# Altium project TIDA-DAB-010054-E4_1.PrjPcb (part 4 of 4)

## Sheet TIDA-DAB-010054-E4_Power Tree.SchDoc
size 431 x 279 mm; Date: Not shown in title block; ApprovedBy: Not shown in title block; CheckedBy: Not shown in title block; Author: Not shown in title block; CompanyName: Not shown in title block; Engineer: Not shown in title block; Organization: Not shown in title block; Address1: Not shown in title block; Address2: Not shown in title block; Address3: Not shown in title block; Address4: Not shown in title block; DocumentNumber: 1; Revision: Use project parameter SCH_Rev; SheetNumber: 9; SheetTotal: 11; PageSetup: Record=PageOptions¦CenterHorizontal=True¦CenterVertical=True¦PrintScale=1.00¦XCorrection=1.00¦YCorrection=1.00¦PrintKind=0¦BorderSize=5000000¦LeftOffset=0¦BottomOffset=0¦Orientation=2¦PaperLength=1000¦PaperWidth=1000¦Scale=100¦PaperSource=15¦PrintQuality=600¦MediaType=1¦DitherType=10¦PaperKind=Letter¦PrintScaleMode=1
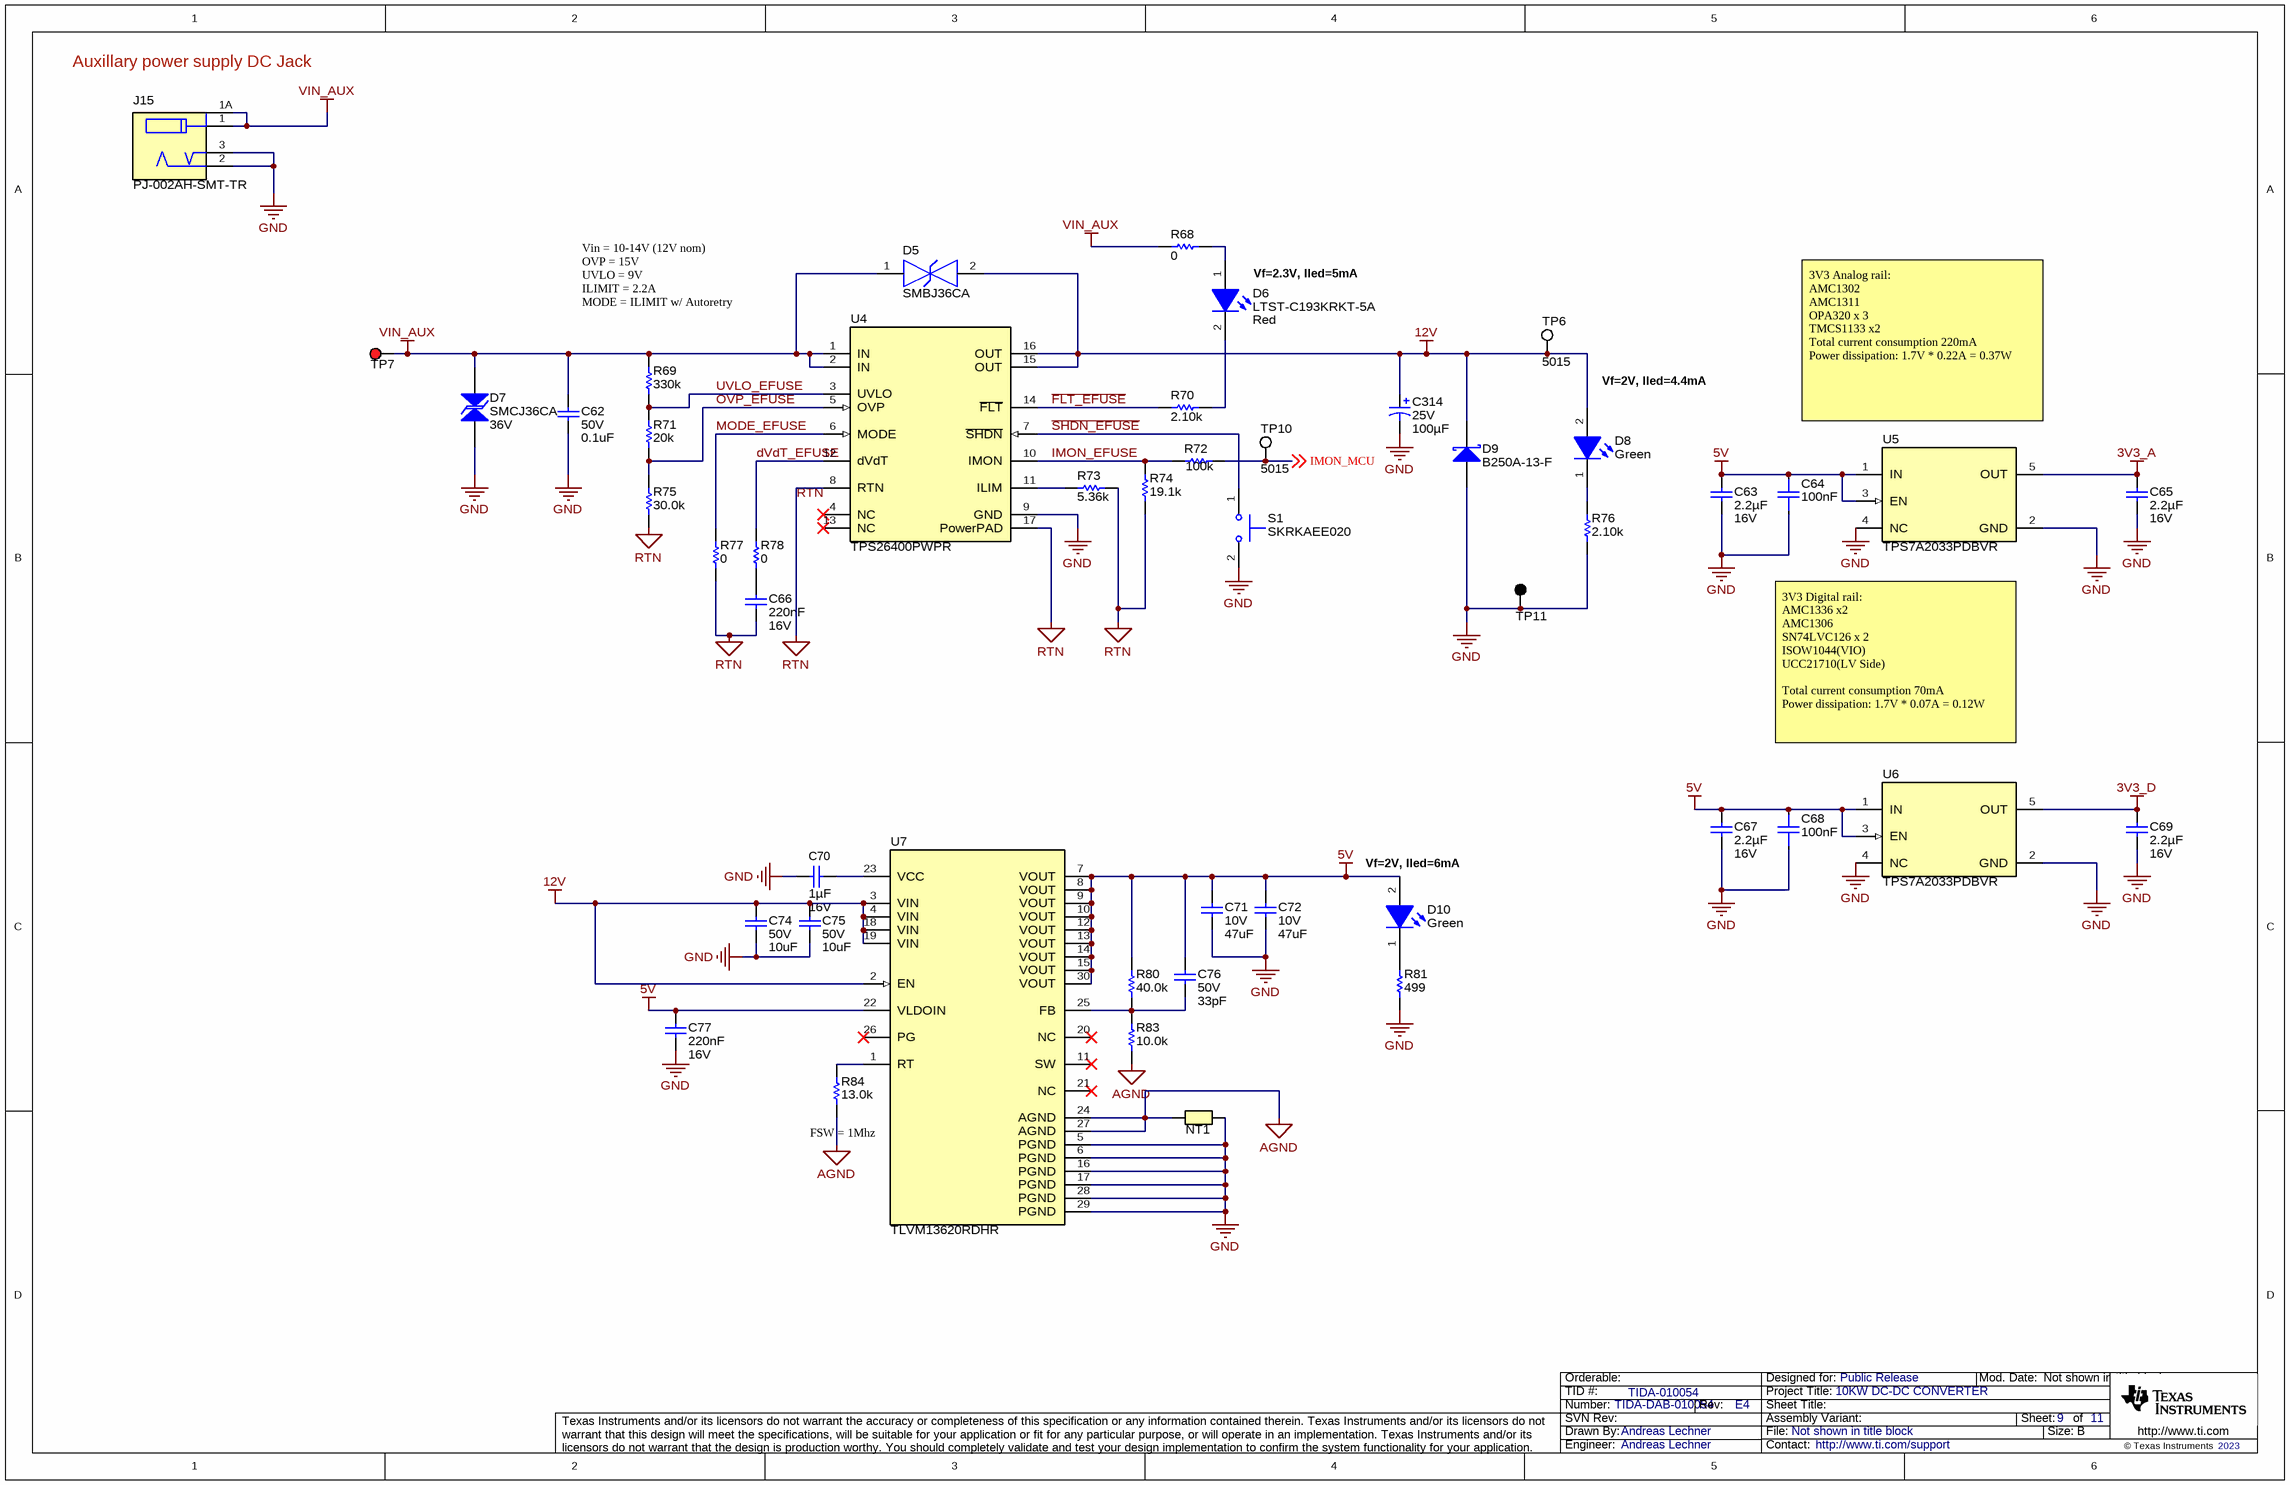
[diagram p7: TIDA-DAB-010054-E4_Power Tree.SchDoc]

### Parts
C62  VDC_V: 50V  ValueDisplayed: 0.1uF  [0402S]  (hidden comment: GCM155R71H104KE02D)
C63  Cap_F: 2.2µF  VDC_V: 16V  [0603]  (hidden comment: EMK107BB7225KA-T)
C64  Cap_F: 100nF  [FP-CL10B104KA8VPJC_0603-MFG]  (hidden comment: CL10B104KA8VPJC)
C65  Cap_F: 2.2µF  VDC_V: 16V  [0603]  (hidden comment: EMK107BB7225KA-T)
C66  Cap_F: 220nF  VDC_V: 16V  [0603]  (hidden comment: C1608X7R1C224K080AC)
C67  Cap_F: 2.2µF  VDC_V: 16V  [0603]  (hidden comment: EMK107BB7225KA-T)
C68  Cap_F: 100nF  [FP-CL10B104KA8VPJC_0603-MFG]  (hidden comment: CL10B104KA8VPJC)
C69  Cap_F: 2.2µF  VDC_V: 16V  [0603]  (hidden comment: EMK107BB7225KA-T)
C70  Cap_F: 1µF  VDC_V: 16V  [0603]  (hidden comment: GCM188R71C105KA64D)
C71  VDC_V: 10V  ValueDisplayed: 47uF  [1210_270]  (hidden comment: GRM32ER71A476KE15L)
C72  VDC_V: 10V  ValueDisplayed: 47uF  [1210_270]  (hidden comment: GRM32ER71A476KE15L)
C74  VDC_V: 50V  ValueDisplayed: 10uF  [1206_180L]  (hidden comment: CL31B106KBHNNNE)
C75  VDC_V: 50V  ValueDisplayed: 10uF  [1206_180L]  (hidden comment: CL31B106KBHNNNE)
C76  VDC_V: 50V  ValueDisplayed: 33pF  [0603]  (hidden comment: GRM1885C1H330JA01D)
C77  Cap_F: 220nF  VDC_V: 16V  [0603]  (hidden comment: C1608X7R1C224K080AC)
C314  VDC_V: 25V  ValueDisplayed: 100µF  [UWT_630x770]  (hidden comment: UWT1E101MCL1GS)
D5  SMBJ36CA  [FP-SMBJ36CA_DO-214AA-0]
D6  LTST-C193KRKT-5A  value Red  [LTST-C193_Red]
D7  SMCJ36CA  value 36V  [SMC_Bi]
D8  value Green  [WL-SMCW_GREEN]  (hidden comment: 150060VS75000)
D9  B250A-13-F  [SMA]
D10  value Green  [WL-SMCW_GREEN]  (hidden comment: 150060VS75000)
J15  PJ-002AH-SMT-TR  [CUI_PJ-002AH-SMT]
NT1  Net-Tie  [Net-Tie7milsWide_20milsLong]  (value not drawn)  (net tie, no BOM)
R68  ValueDisplayed: 0  [0603]  (hidden comment: RC0603JR-070RL)
R69  ValueDisplayed: 330k  [0603]  (hidden comment: RC0603FR-07330KL)
R70  ValueDisplayed: 2.10k  [0603]  (hidden comment: RC0603FR-072K1L)
R71  ValueDisplayed: 20k  [0603]  (hidden comment: RC0603JR-0720KL)
R72  ValueDisplayed: 100k  [0603]  (hidden comment: CRCW0603100KJNEA)
R73  ValueDisplayed: 5.36k  [0603]  (hidden comment: CRCW06035K36FKEA)
R74  ValueDisplayed: 19.1k  [0603]  (hidden comment: RC0603FR-0719K1L)
R75  ValueDisplayed: 30.0k  [0603]  (hidden comment: RC0603FR-0730KL)
R76  ValueDisplayed: 2.10k  [0603]  (hidden comment: RC0603FR-072K1L)
R77  ValueDisplayed: 0  [0603]  (hidden comment: RC0603JR-070RL)
R78  ValueDisplayed: 0  [0603]  (hidden comment: RC0603JR-070RL)
R80  ValueDisplayed: 40.0k  [0603]  (hidden comment: PAT0603E4002BST1)
R81  ValueDisplayed: 499  [0603]  (hidden comment: CRCW0603499RFKEAC)
R83  ValueDisplayed: 10.0k  [0603]  (hidden comment: RG1608P-103-B-T5)
R84  ValueDisplayed: 13.0k  [0603]  (hidden comment: RC0603FR-0713KL)
S1  SKRKAEE020  [SW_SKRKAE]
TP6  5015  [Testpoint_Keystone_Miniature]
TP7  5010  [Keystone5010]  (value not drawn)
TP10  5015  [Testpoint_Keystone_Miniature]
TP11  5011  [Keystone5011]  (value not drawn)
U4  TPS26400PWPR  [PWP0016H-MFG]
U5  TPS7A2033PDBVR  [DBV0005A-MFG]
U6  TPS7A2033PDBVR  [DBV0005A-MFG]
U7  TLVM13620RDHR  [RDH0030A-MFG]

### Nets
3V3_A: C65.1 U5.5(OUT)
3V3_D: C69.1 U6.5(OUT)
5V: C63.1 C64.2 C67.1 C68.2 C71.1 C72.1 C76.1 C77.1 D10.2(A) R80.2 U5.1(IN) U5.3(EN) U6.1(IN) U6.3(EN) U7.7(VOUT) U7.8(VOUT) U7.9(VOUT) U7.10(VOUT) U7.12(VOUT) U7.13(VOUT) U7.14(VOUT) U7.15(VOUT) U7.22(VLDOIN) U7.30(VOUT)
12V: C74.1 C75.1 C314.1(+) D5.2 D8.2(A) D9.1(K) TP6.1 U4.15(OUT) U4.16(OUT) U7.2(EN) U7.3(VIN) U7.4(VIN) U7.18(VIN) U7.19(VIN)
AGND: NT1.2 R83.2 R84.1 U7.24(AGND) U7.27(AGND)
GND: C62.2 C63.2 C64.1 C65.2 C67.2 C68.1 C69.2 C70.1 C71.2 C72.2 C74.2 C75.2 C77.2 C314.2(-) D7.1 D9.2(A) J15.2 J15.3 NT1.1 R76.1 R81.1 S1.2 TP11.1 U4.9(GND) U5.2(GND) U5.4(NC) U6.2(GND) U6.4(NC) U7.5(PGND) U7.6(PGND) U7.16(PGND) U7.17(PGND) U7.28(PGND) U7.29(PGND)
RTN: C66.2 R73.2 R74.1 R75.1 R77.1 U4.8(RTN) U4.17(PowerPAD)
VIN_AUX: C62.1 D5.1 D7.2 J15.1 J15.1A R68.2 R69.2 TP7.1 U4.1(IN) U4.2(IN)
~{FLT_EFUSE}: R70.1 U4.14(~{FLT})
~{SHDN_EFUSE}: S1.1 U4.7(~{SHDN})
dVdT_EFUSE: R78.2 U4.12(dVdT)
IMON_EFUSE: R72.1 R74.2 U4.10(IMON)
IMON_MCU: R72.2 TP10.1 ; off-sheet IMON_MCU
MODE_EFUSE: R77.2 U4.6(MODE)
OVP_EFUSE: R71.1 R75.2 U4.5(OVP)
UVLO_EFUSE: R69.1 R71.2 U4.3(UVLO)
NetC66_1: C66.1 R78.1
NetC70_2: C70.2 U7.23(VCC)
NetC76_2: C76.2 R80.1 R83.1 U7.25(FB)
NetD6_1: D6.1(A) R68.1
NetD6_2: D6.2(K) R70.2
NetD8_1: D8.1(K) R76.2
NetD10_1: D10.1(K) R81.2
NetR73_1: R73.1 U4.11(ILIM)
NetR84_2: R84.2 U7.1(RT)

Not connected (* = marked no-connect by the designer): U4 4(NC)* 13(NC)*; U7 11(SW)* 20(NC)* 21(NC)* 26(PG)*

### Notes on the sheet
- (near J15) Auxillary power supply DC Jack
- (near D6) Vf=2.3V, Iled=5mA
- (near R69) Vin = 10-14V (12V nom)
  OVP = 15V
  UVLO = 9V
  ILIMIT = 2.2A
  MODE = ILIMIT w/ Autoretry
- Vf=2V, Iled=4.4mA
- 3V3 Analog rail:
  AMC1302
  AMC1311
  OPA320 x 3
  TMCS1133 x2
  Total current consumption 220mA
  Power dissipation: 1.7V * 0.22A = 0.37W
- 3V3 Digital rail:
  AMC1336 x2
  AMC1306
  SN74LVC126 x 2
  ISOW1044(VIO)
  UCC21710(LV Side)
  Total current consumption 70mA
  Power dissipation: 1.7V * 0.07A = 0.12W
- (near D10) Vf=2V, Iled=6mA
- (near U7) FSW = 1Mhz

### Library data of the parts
C62 = CMP-0006356-2: CAP, CERM, 0.1 uF, 50 V, +/- 10%, X7R, AEC-Q200 Grade 1, 0402; Manufacturer: MuRata; TaMin_C: -55°C; Polarized: N; SizeAreaWB_mm2: 3; Value1: Unknown; U/M: EA; Value: 0.1uF; TaMax_C: 125°C; SizeZ_mm: 0.6; SizeX_mm: 1; SizeY_mm: 0.5; Cap_Case: 0402; AEC Qualified: Y; Cap_F: 100nF; AEC Category: Q200
C63 C65 C67 C69 = CMP-0007121-4: CAP, CERM, 2.2 uF, 16 V, +/- 10%, X7R, 0603; Manufacturer: Taiyo Yuden; TaMin_C: -55°C; Polarized: N; SizeAreaWB_mm2: 4.68; Value1: Unknown; U/M: EA; Value: 2.2uF; TaMax_C: 125°C; SizeZ_mm: 1; SizeX_mm: 1.6; SizeY_mm: 0.8; SizeArea_mm2: 1.28; AEC Category: Q200
C64 C68 = CMP-0121051-1: Automotive CAP, 100㎋, 25V, ±10%, X7R, 0603, 5mm Bending; Manufacturer: Samsung; AEC Grade: Grade 1; AEC Qualified: Yes; SizeZ_mm: 0.9mm; TempCo: 15%; Value: 100nF
C66 C77 = CMP-0007038-5: CAP, CERM, 0.22 uF, 16 V, +/- 10%, X7R, 0603; Manufacturer: TDK; TaMin_C: -55°C; ESR_ohm: 0.0125; Polarized: N; SizeAreaWB_mm2: 4.68; Value1: 0.0125 ohm; U/M: EA; Value: 0.22uF; TaMax_C: 125°C; SizeZ_mm: 1; SizeX_mm: 1.6; SizeY_mm: 0.8; SizeArea_mm2: 1.28; AEC Category: Q200
C70 = CMP-0007136-5: CAP, CERM, 1 uF, 16 V, +/- 10%, X7R, AEC-Q200 Grade 1, 0603; Manufacturer: MuRata; TaMin_C: -55°C; Polarized: N; SizeAreaWB_mm2: 4.68; Value1: Unknown; U/M: EA; Value: 1uF; TaMax_C: 125°C; SizeZ_mm: 1; SizeX_mm: 1.6; SizeY_mm: 0.8; SizeArea_mm2: 1.28; AEC Qualified: Y; AEC Category: Q200
C71 C72 = CMP-0009220-2: CAP, CERM, 47 uF, 10 V, +/- 10%, X7R, 1210; Manufacturer: MuRata; TaMin_C: -55°C; Polarized: N; SizeAreaWB_mm2: 14.7; Value1: Unknown; U/M: EA; Value: 47uF; TaMax_C: 125°C; SizeZ_mm: 2.7; SizeX_mm: 3.2; SizeY_mm: 2.5; Cap_Case: 1210; SizeArea_mm2: 8; Cap_F: 47µF; AEC Category: Q200
C74 C75 = CMP-0008802-2: CAP, CERM, 10 uF, 50 V, +/- 10%, X7R, 1206; Manufacturer: Samsung; TaMin_C: -55°C; Polarized: N; SizeAreaWB_mm2: 10.92; Value1: Unknown; U/M: EA; Value: 10uF; TaMax_C: 125°C; SizeZ_mm: 1.8; SizeX_mm: 3.2; SizeY_mm: 1.6; Cap_Case: 1206; SizeArea_mm2: 5.12; Cap_F: 10µF; AEC Category: Q200
C76 = CMP-0007208-4: CAP, CERM, 33 pF, 50 V, +/- 5%, C0G/NP0, 0603; Manufacturer: MuRata; TaMin_C: -55°C; Polarized: N; SizeAreaWB_mm2: 4.68; Value1: Unknown; U/M: EA; Value: 33pF; TaMax_C: 125°C; SizeZ_mm: 1; SizeX_mm: 1.6; SizeY_mm: 0.8; SizeArea_mm2: 1.28; AEC Category: Q200
C314 = CMP-0081462-1: CAP, AL, 100 µF, 25 V, +/- 20%, SMD; Manufacturer: Nichicon; TaMin_C: -55°C; Polarized: Y; SizeAreaWB_mm2: 77.4; U/M: EA; Value: 100uF; TaMax_C: 105°C; SizeZ_mm: 8; SizeX_mm: 7; SizeY_mm: 6.6; Cap_Case: 6.3x7.7mm; SizeArea_mm2: 46.2; CompType: Capacitor; AEC Qualified: N; IRMS_A: 91mA; AEC Category: Q200
D5 = CMP-0086728-1: Diode TVS Single Bi-Dir 36V 600W 2-Pin SMB; Manufacturer: Littelfuse; SizeZ_mm: 2.61mm; Ipp: 10.4µA
D6 = CMP-0079922-3: LED, Red, SMD; Manufacturer: Lite-On; SizeX_mm: 1.6; Value2: 2V; SizeY_mm: 0.8; Green_REACh: Incomplete; SizeAreaWB_mm2: 4.68; Green_Lifecycle: Not Set; Value1: W; Io_A: 5mA; Type: AlInGaP; SizeZ_mm: 0.45; Tjmax_C: 85°C; SizeArea_mm2: 1.28
D7 = CMP-0005697-3: Diode, TVS, Bi, 36 V, 58.1 Vc, SMC; Manufacturer: Littelfuse; Ppk: 1.5kW; Vbr_Min: 40V; SizeX_mm: 8.13; SizeZ_mm: 2.6; SizeAreaWB_mm2: 83.2686; RJA_CperW: 75; AEC Category: Q101; Vbr_Max: 44.2V; SizeArea_mm2: 50.5686; Ipp: 25.9A; Vc: 58.1V; AEC Qualified: N; Value1: 1500W; SizeY_mm: 6.22
D8 D10 = CMP-0002894-2: LED, Green, SMD; Manufacturer: Wurth Elektronik; Type: AlInGaP; Value2: 2V; Io_A: 20mA; Value1: W
D9 = CMP-0028405-2: Diode, Schottky, 50 V, 2 A, SMA; Manufacturer: Diodes Inc.; SizeArea_mm2: 16.3228; RJC_CperW: 20; Vr_V: 50V; SizeX_mm: 5.59; Green_REACh: Incomplete; SizeY_mm: 2.92; Green_Lifecycle: Not Set; Value2: 0.7V; Io_A: 2A; Value: 50V; SizeZ_mm: 2.87; SizeAreaWB_mm2: 37.3428; AEC Category: Q101; TJmax_C: 150°C; Vf_V: 700mV
J15 = CMP-0075012-1: Power Jack, SMT; Manufacturer: CUI Inc.; Green_Lifecycle: Not Set; Green_REACh: Incomplete; CNHeader: False
NT1 = CMP-0078142-5: Single point connection between nets.
R68 R77 R78 = CMP-0025885-5: RES, 0, 5%, 0.1 W, 0603; Manufacturer: Yageo; Power_W: 100mW; TempCo: 200 ppm/C; Value_Code: 0000; Value: 0; EIA_Code: E24; SizeX_mm: 1.6; SizeZ_mm: 1; Value2: 0.1W; SizeArea_mm2: 1.28; AEC Qualified: N; VDC_V: 75V; AEC Category: Q200; SizeY_mm: 0.8; SizeAreaWB_mm2: 4.68
R69 = CMP-0023032-4: RES, 330 k, 1%, 0.1 W, 0603; Manufacturer: Yageo; Power_W: 100mW; TempCo: 100 ppm/C; Value: 330k; SizeX_mm: 1.6; SizeY_mm: 0.8; SizeZ_mm: 1; Value2: 0.1W; SizeArea_mm2: 1.28; AEC Qualified: N; VDC_V: 75V; AEC Category: Q200; SizeAreaWB_mm2: 4.68
R70 R76 = CMP-0022983-5: RES, 2.10 k, 1%, 0.1 W, 0603; Manufacturer: Yageo; Power_W: 100mW; TempCo: 100 ppm/C; Value_Code: 2k10; Value: 2.10k; EIA_Code: E96; Res_ohm: 2.1k; SizeX_mm: 1.6; SizeY_mm: 0.8; SizeZ_mm: 1; Value2: 0.1W; SizeArea_mm2: 1.28; AEC Qualified: N; VDC_V: 75V; AEC Category: Q200; SizeAreaWB_mm2: 4.68
R71 = CMP-0025900-5: RES, 20 k, 5%, 0.1 W, 0603; Manufacturer: Yageo; Power_W: 100mW; TempCo: 100 ppm/C; Value_Code: 20k0; Value: 20k; EIA_Code: E24; SizeX_mm: 1.6; SizeY_mm: 0.8; SizeZ_mm: 1; Value2: 0.1W; SizeArea_mm2: 1.28; AEC Qualified: N; VDC_V: 75V; AEC Category: Q200; SizeAreaWB_mm2: 4.68
R72 = CMP-0025698-4: RES, 100 k, 5%, 0.1 W, AEC-Q200 Grade 0, 0603; Manufacturer: Vishay-Dale; Power_W: 100mW; TempCo: 200 ppm/C; Value: 100k; EIA_Code: E24; SizeX_mm: 1.6; SizeY_mm: 0.8; SizeZ_mm: 1; Value2: 0.1W; SizeArea_mm2: 1.28; AEC Qualified: Y; VDC_V: 75V; AEC Category: Q200; AEC Grade: 0
R73 = CMP-0022511-4: RES, 5.36 k, 1%, 0.1 W, AEC-Q200 Grade 0, 0603; Manufacturer: Vishay-Dale; Power_W: 100mW; TempCo: 100 ppm/C; Value_Code: 5k36; Value: 5.36k; EIA_Code: E96; SizeX_mm: 1.6; SizeY_mm: 0.8; SizeZ_mm: 1; Value2: 0.1W; SizeArea_mm2: 1.28; AEC Qualified: Y; VDC_V: 75V; AEC Category: Q200; AEC Grade: 0
R74 = CMP-0022860-5: RES, 19.1 k, 1%, 0.1 W, 0603; Manufacturer: Yageo; Power_W: 100mW; TempCo: 100 ppm/C; Value_Code: 19k1; Value: 19.1k; EIA_Code: E96; SizeX_mm: 1.6; SizeY_mm: 0.8; SizeZ_mm: 1; Value2: 0.1W; SizeArea_mm2: 1.28; AEC Qualified: N; VDC_V: 75V; AEC Category: Q200; SizeAreaWB_mm2: 4.68
R75 = CMP-0023020-5: RES, 30.0 k, 1%, 0.1 W, 0603; Manufacturer: Yageo; Power_W: 100mW; TempCo: 100 ppm/C; Value_Code: 30k0; Value: 30.0k; Res_ohm: 30k; SizeX_mm: 1.6; SizeY_mm: 0.8; SizeZ_mm: 1; Value2: 0.1W; SizeArea_mm2: 1.28; AEC Qualified: N; VDC_V: 75V; AEC Category: Q200; SizeAreaWB_mm2: 4.68
R80 = CMP-0860025-1: RES, 40.0 k, 0.1%, 0.15 W, AEC-Q200 Grade 0, 0603; Manufacturer: Vishay Thin Film; SizeArea_mm2: 1.28; AEC Grade: 0; SizeAreaWB_mm2: 4.68; Value: 40.0k; Value_Code: 40k0; SizeZ_mm: 1; AEC Qualified: Y; AEC Category: Q200; Power_W: 150mW; SizeY_mm: 0.8; SizeX_mm: 1.6; TempCo: 25 ppm/C; Value2: 0.15W; Res_ohm: 40k
R81 = CMP-0082532-1: RES, 499, 1%, 0.1 W, 0603; Manufacturer: Vishay-Dale; Power_W: 100mW; TempCo: 100 ppm/C; SizeAreaWB_mm2: 4.68; Value_Code: 499R; Value: 499; EIA_Code: E96; SizeX_mm: 1.6; SizeY_mm: 0.8; SizeZ_mm: 1; Value2: 0.1W; SizeArea_mm2: 1.28; AEC Qualified: N; VDC_V: 75V; AEC Category: Q200
R83 = CMP-0023404-3: RES, 10.0 k, 0.1%, 0.1 W, 0603; Manufacturer: Susumu Co Ltd; Power_W: 100mW; TempCo: 25 ppm/C; Value_Code: 10k0; U/M: EA; Value: 10.0k; EIA_Code: E192; Res_ohm: 10k; SizeX_mm: 1.6; SizeY_mm: 0.8; SizeZ_mm: 1; Value2: 0.1W; SizeArea_mm2: 1.28; VDC_V: 75V; AEC Category: Q200
R84 = CMP-0022792-5: RES, 13.0 k, 1%, 0.1 W, 0603; Manufacturer: Yageo; Power_W: 100mW; TempCo: 100 ppm/C; Value_Code: 13k0; Value: 13.0k; EIA_Code: E96; Res_ohm: 13k; SizeX_mm: 1.6; SizeY_mm: 0.8; SizeZ_mm: 1; Value2: 0.1W; SizeArea_mm2: 1.28; AEC Qualified: N; VDC_V: 75V; AEC Category: Q200; SizeAreaWB_mm2: 4.68
S1 = CMP-0085606-1: Switch, SPST-NO, 0.05 A, 12 VDC, SMT; Manufacturer: Alps; SizeX_mm: 4.8; SizeZ_mm: 2.2; SizeArea_mm2: 13.92; SizeY_mm: 2.9; PositionCount: 1; SizeAreaWB_mm2: 22.62; VDC_V: 12V; CurrentRating_mA: 50A
TP6 TP10 = CMP-0055152-2: Test Point, Miniature, SMT; Manufacturer: Keystone Electronics; CT: TRUE; Green_Lifecycle: Active; Green_REACh: Passed; CNHeader: FALSE
TP7 = CMP-0055147-2: Test Point, Multipurpose, Red, TH; Manufacturer: Keystone Electronics; CT: TRUE; ContactFinish: Silver; Green_Lifecycle: Active; CNHeader: FALSE; Green_REACh: Passed
TP11 = CMP-0055148-2: Test Point, Multipurpose, Black, TH; Manufacturer: Keystone Electronics; CNHeader: FALSE; ContactFinish: Silver; Green_REACh: Passed; Green_Lifecycle: Active; CT: TRUE
U4 = CMP-0089748-2: 42-V, 2-A Industrial eFuse With Integrated Reverse Input Polarity Protection; Manufacturer: Texas Instruments; Number Of Channels: 1; CompType: IC; Max Supply Voltage: 42V; AEC Category: Q200; TJmax_C: +125°C; Standoff Height: 0.05mm; SizeZ_mm: 1.2mm; AEC Qualified: No
U5 U6 = CMP-0092532-1: 300-mA, Ultra-Low-Noise, Low-IQ, High PSRR LDO; Manufacturer: Texas Instruments; TJmax_C: +125°C; Min Supply Voltage: 1.6V; SizeZ_mm: 1.45mm; Output Voltage: 3.3V; Number Of Outputs: 1; Nominal Supply Current: 6.5uA; AEC Qualified: No; Accuracy Percentage: 1.5%; Max Supply Voltage: 6V; Dropout Voltage: 145mV; Standoff Height: 0mm; Output Type: Fixed
U7 = CMP-0097291-1: High-Density, 3-V to 36-V Input, 1-V to 6-V Output, 2-A Power Module With Enhanced HotRod™ QFN Package; Manufacturer: Texas Instruments; AEC Qualified: No; Number Of Outputs: 1; TaMax_C: +105°C; Switching Topology: Buck; Output Voltage: 1-6V; TaMin_C: -40°C; Max Supply Voltage: 36V; TJmax_C: +125°C; Switching Frequency: 200-2200kHz; Min Supply Voltage: 3V; SizeZ_mm: 1.9mm; Nominal Supply Current: 4uA; Standoff Height: 0mm; Output Type: AdjustableProgrammable

## Sheet TIDA-DAB-010054-E4_Control Card.SchDoc
size 431 x 279 mm; Date: Not shown in title block; ApprovedBy: Not shown in title block; CheckedBy: Not shown in title block; Author: Not shown in title block; CompanyName: Not shown in title block; Engineer: Not shown in title block; Organization: Not shown in title block; Address1: Not shown in title block; Address2: Not shown in title block; Address3: Not shown in title block; Address4: Not shown in title block; DocumentNumber: 1; Revision: Use project parameter SCH_Rev; SheetNumber: 10; SheetTotal: 11; PageSetup: Record=PageOptions¦CenterHorizontal=True¦CenterVertical=True¦PrintScale=1.00¦XCorrection=1.00¦YCorrection=1.00¦PrintKind=0¦BorderSize=5000000¦LeftOffset=0¦BottomOffset=0¦Orientation=2¦PaperLength=1000¦PaperWidth=1000¦Scale=100¦PaperSource=15¦PrintQuality=600¦MediaType=1¦DitherType=10¦PaperKind=Letter¦PrintScaleMode=1
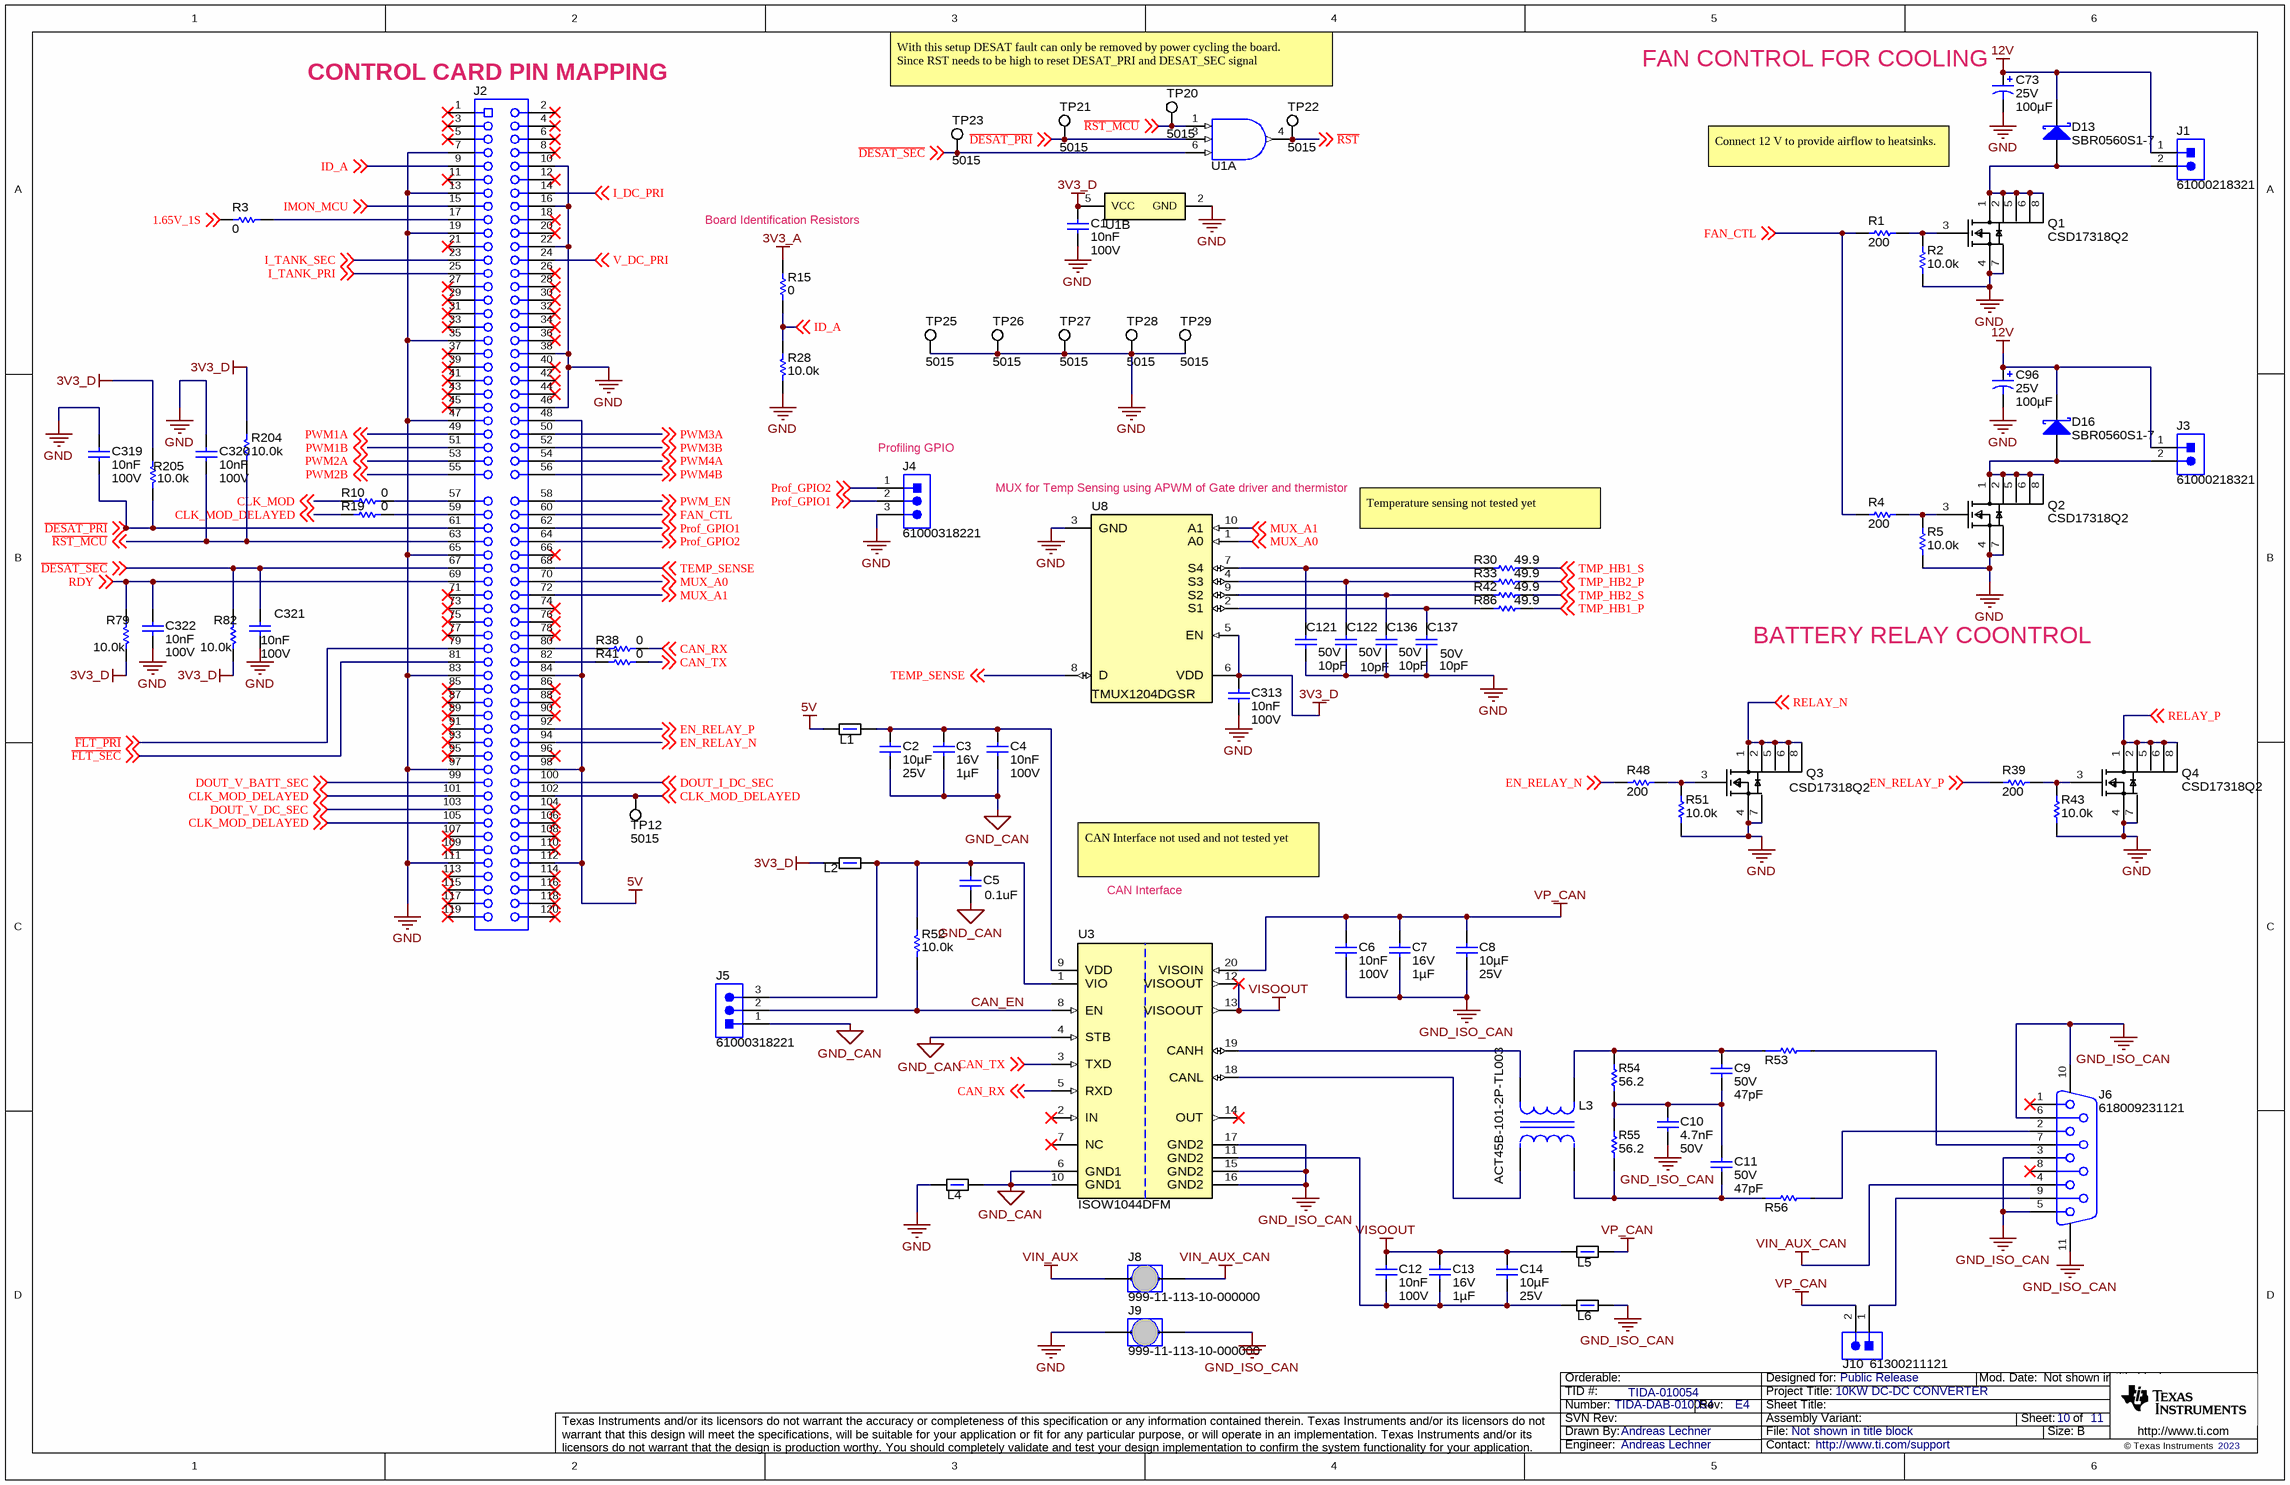
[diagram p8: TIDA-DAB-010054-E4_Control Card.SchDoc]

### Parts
C1  Cap_F: 10nF  VDC_V: 100V  [0603]  (hidden comment: C0603C103J1RACTU)
C2  ValueDisplayed: 10µF  VDC_V: 25V  [1206_180L]  (hidden comment: C3216X7R1E106K160AB)
C3  VDC_V: 16V  Cap_F: 1µF  [0603]  (hidden comment: CL10B105KO8VPNC)
C4  Cap_F: 10nF  VDC_V: 100V  [0603]  (hidden comment: C0603C103J1RACTU)
C5  ValueDisplayed: 0.1uF  [0603]  (hidden comment: 885012206095)
C6  Cap_F: 10nF  VDC_V: 100V  [0603]  (hidden comment: C0603C103J1RACTU)
C7  VDC_V: 16V  Cap_F: 1µF  [0603]  (hidden comment: CL10B105KO8VPNC)
C8  ValueDisplayed: 10µF  VDC_V: 25V  [1206_180L]  (hidden comment: C3216X7R1E106K160AB)
C9  VDC_V: 50V  ValueDisplayed: 47pF  [0603]  (hidden comment: GRM1885C1H470JA01D)
C10  Cap_F: 4.7nF  VDC_V: 50V  [0603]  (hidden comment: C0603X472K5RACTU)
C11  VDC_V: 50V  ValueDisplayed: 47pF  [0603]  (hidden comment: GRM1885C1H470JA01D)
C12  Cap_F: 10nF  VDC_V: 100V  [0603]  (hidden comment: C0603C103J1RACTU)
C13  VDC_V: 16V  Cap_F: 1µF  [0603]  (hidden comment: CL10B105KO8VPNC)
C14  ValueDisplayed: 10µF  VDC_V: 25V  [1206_180L]  (hidden comment: C3216X7R1E106K160AB)
C73  VDC_V: 25V  ValueDisplayed: 100µF  [UWT_630x770]  (hidden comment: UWT1E101MCL1GS)
C96  VDC_V: 25V  ValueDisplayed: 100µF  [UWT_630x770]  (hidden comment: UWT1E101MCL1GS)
C121  VDC_V: 50V  ValueDisplayed: 10pF  [0603]  (hidden comment: C0603C100J5GACTU)
C122  VDC_V: 50V  ValueDisplayed: 10pF  [0603]  (hidden comment: C0603C100J5GACTU)
C136  VDC_V: 50V  ValueDisplayed: 10pF  [0603]  (hidden comment: C0603C100J5GACTU)
C137  VDC_V: 50V  ValueDisplayed: 10pF  [0603]  (hidden comment: C0603C100J5GACTU)
C313  Cap_F: 10nF  VDC_V: 100V  [0603]  (hidden comment: C0603C103J1RACTU)
C319  Cap_F: 10nF  VDC_V: 100V  [0603]  (hidden comment: C0603C103J1RACTU)
C320  Cap_F: 10nF  VDC_V: 100V  [0603]  (hidden comment: C0603C103J1RACTU)
C321  Cap_F: 10nF  VDC_V: 100V  [0603]  (hidden comment: C0603C103J1RACTU)
C322  Cap_F: 10nF  VDC_V: 100V  [0603]  (hidden comment: C0603C103J1RACTU)
D13  SBR0560S1-7  [SOD-123]
D16  SBR0560S1-7  [SOD-123]
J1  61000218321  [Wurth_61000218321]
J2  HSEC8-160-01-L-DV-A-BL  [controlCARD-120HSEC]  (value not drawn)
J3  61000218321  [Wurth_61000218321]
J4  61000318221  [Wurth_61000318221]
J5  61000318221  [Wurth_61000318221]
J6  618009231121  [Wurth_618009231121]
J8  999-11-113-10-000000  [Mill-Max_999-11-113-10-000000]
J9  999-11-113-10-000000  [Mill-Max_999-11-113-10-000000]
J10  61300211121  [WURTH_61300211121]
L1  74279228260  [0603]  (value not drawn)
L2  74279228260  [0603]  (value not drawn)
L3  ACT45B-101-2P-TL003  [FP-ACT45B-101-2P-TL003_SMT_4MM5_3MM2-MFG]
L4  74279228260  [0603]  (value not drawn)
L5  74279228260  [0603]  (value not drawn)
L6  74279228260  [0603]  (value not drawn)
Q1  CSD17318Q2  [FP-CSD17318Q2_WSON6-MFG]
Q2  CSD17318Q2  [FP-CSD17318Q2_WSON6-MFG]
Q3  CSD17318Q2  [FP-CSD17318Q2_WSON6-MFG]
Q4  CSD17318Q2  [FP-CSD17318Q2_WSON6-MFG]
R1  ValueDisplayed: 200  [0603]  (hidden comment: RT0603BRD07200RL)
R2  ValueDisplayed: 10.0k  [0603]  (hidden comment: RT0603BRD0710KL)
R3  ValueDisplayed: 0  [0603]  (hidden comment: RMCF0603ZT0R00)
R4  ValueDisplayed: 200  [0603]  (hidden comment: RT0603BRD07200RL)
R5  ValueDisplayed: 10.0k  [0603]  (hidden comment: RT0603BRD0710KL)
R10  ValueDisplayed: 0  [0603]  (hidden comment: RMCF0603ZT0R00)
R15  ValueDisplayed: 0  [0603]  (hidden comment: RMCF0603ZT0R00)
R19  ValueDisplayed: 0  [0603]  (hidden comment: RMCF0603ZT0R00)
R28  ValueDisplayed: 10.0k  [0603]  (hidden comment: CRCW060310K0FKEA)
R30  ValueDisplayed: 49.9  [0603]  (hidden comment: RC0603FR-0749R9L)
R33  ValueDisplayed: 49.9  [0603]  (hidden comment: RC0603FR-0749R9L)
R38  ValueDisplayed: 0  [0603]  (hidden comment: RMCF0603ZT0R00)
R39  ValueDisplayed: 200  [0603]  (hidden comment: RT0603BRD07200RL)
R41  ValueDisplayed: 0  [0603]  (hidden comment: RMCF0603ZT0R00)
R42  ValueDisplayed: 49.9  [0603]  (hidden comment: RC0603FR-0749R9L)
R43  ValueDisplayed: 10.0k  [0603]  (hidden comment: RT0603BRD0710KL)
R48  ValueDisplayed: 200  [0603]  (hidden comment: RT0603BRD07200RL)
R51  ValueDisplayed: 10.0k  [0603]  (hidden comment: RT0603BRD0710KL)
R52  ValueDisplayed: 10.0k  [0603]  (hidden comment: CRCW060310K0FKEA)
R53  CR0603-10W-000T  [FP-CR0603-10W-000T_0603-MFG]  (value not drawn)
R54  ValueDisplayed: 56.2  [0603]  (hidden comment: CRCW060356R2FKEA)
R55  ValueDisplayed: 56.2  [0603]  (hidden comment: CRCW060356R2FKEA)
R56  CR0603-10W-000T  [FP-CR0603-10W-000T_0603-MFG]  (value not drawn)
R79  ValueDisplayed: 10.0k  [0603]  (hidden comment: CRCW060310K0FKEA)
R82  ValueDisplayed: 10.0k  [0603]  (hidden comment: CRCW060310K0FKEA)
R86  ValueDisplayed: 49.9  [0603]  (hidden comment: RC0603FR-0749R9L)
R204  ValueDisplayed: 10.0k  [0603]  (hidden comment: CRCW060310K0FKEA)
R205  ValueDisplayed: 10.0k  [0603]  (hidden comment: CRCW060310K0FKEA)
TP12  5015  [Testpoint_Keystone_Miniature]
TP20  5015  [Testpoint_Keystone_Miniature]
TP21  5015  [Testpoint_Keystone_Miniature]
TP22  5015  [Testpoint_Keystone_Miniature]
TP23  5015  [Testpoint_Keystone_Miniature]
TP25  5015  [Testpoint_Keystone_Miniature]
TP26  5015  [Testpoint_Keystone_Miniature]
TP27  5015  [Testpoint_Keystone_Miniature]
TP28  5015  [Testpoint_Keystone_Miniature]
TP29  5015  [Testpoint_Keystone_Miniature]
U1  SN74LVC1G11DBVR  [DBV0006A_N]  (value not drawn)  (parts A,B of 2)
U3  ISOW1044DFM  [DFM0020A-MFG]
U8  TMUX1204DGSR  [DGS0010A-MFG]

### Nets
1.65V_1S: R3.1 ; off-sheet 1.65V_1S  [project net 1V65_1]
3V3_A: R15.2
3V3_D: C1.1 C313.1 L2.2 R79.1 R82.1 R204.1 R205.1 U1.5(VCC) U8.5(EN) U8.6(VDD)
5V: J2.48 J2.84 J2.98 J2.112 L1.2
12V: C73.1(+) C96.1(+) D13.1(K) D16.1(K) J1.1 J3.1
GND: C1.2 C73.2(-) C96.2(-) C121.2 C122.2 C136.2 C137.2 C313.2 C319.1 C320.1 C321.2 C322.2 J2.7 J2.10 J2.13 J2.16 J2.19 J2.22 J2.35 J2.38 J2.46 J2.47 J2.65 J2.83 J2.97 J2.111 J4.3 J9.1 L4.2 Q1.4(S) Q1.7(S) Q2.4(S) Q2.7(S) Q3.4(S) Q3.7(S) Q4.4(S) Q4.7(S) R2.1 R5.1 R28.2 R43.1 R51.1 TP25.1 TP26.1 TP27.1 TP28.1 TP29.1 U1.2(GND) U8.3(GND)
GND_CAN: C2.2 C3.2 C4.2 C5.2 J5.1 L4.1 U3.4(STB) U3.6(GND1) U3.10(GND1)
GND_ISO_CAN: C6.2 C7.2 C8.2 C10.1 J6.3 J6.5 J6.6 J6.10 J6.11 J9.2 L6.1 U3.15(GND2) U3.16(GND2) U3.17(GND2)
VIN_AUX: J8.1
VIN_AUX_CAN: J6.4 J8.2
VISOOUT: C12.1 C13.1 C14.1 L5.2 U3.12(VISOOUT) U3.13(VISOOUT)
VP_CAN: C6.1 C7.1 C8.1 J10.2 L5.1 U3.20(VISOIN)
~{DESAT_PRI}: C319.2 J2.61 R205.2 TP21.1 U1.3(B) ; off-sheet ~{DESAT_PRI}
~{DESAT_SEC}: C321.1 J2.67 R82.2 TP23.1 U1.6(C) ; off-sheet ~{DESAT_SEC}
~{FLT_PRI}: J2.79 ; off-sheet ~{FLT_PRI}
~{FLT_SEC}: J2.81 ; off-sheet ~{FLT_SEC}
~{RST}: TP22.1 U1.4(Y) ; off-sheet ~{RST}
~{RST_MCU}: C320.2 J2.63 R204.2 TP20.1 U1.1(A) ; off-sheet ~{RST_MCU}
CAN_EN: J5.2 R52.2 U3.8(EN)
CAN_RX: R38.2 U3.5(RXD) ; off-sheet CAN_RX
CAN_TX: R41.2 U3.3(TXD) ; off-sheet CAN_TX
CLK_MOD: R10.1 ; off-sheet CLK_MOD
CLK_MOD_DELAYED: J2.101 J2.102 J2.105 R19.1 TP12.1 ; off-sheet CLK_MOD_DELAYED
DOUT_I_DC_SEC: J2.100 ; off-sheet DOUT_I_DC_SEC
DOUT_V_BATT_SEC: J2.99 ; off-sheet DOUT_V_BATT_SEC
DOUT_V_DC_SEC: J2.103 ; off-sheet DOUT_V_DC_SEC
EN_RELAY_N: J2.94 R48.1 ; off-sheet EN_RELAY_N
EN_RELAY_P: J2.92 R39.1 ; off-sheet EN_RELAY_P
FAN_CTL: J2.60 R1.1 R4.1 ; off-sheet FAN_CTL
I_DC_PRI: J2.14 ; off-sheet I_DC_PRI
I_TANK_PRI: J2.25 ; off-sheet I_TANK_PRI
I_TANK_SEC: J2.23 ; off-sheet I_TANK_SEC
ID_A: J2.9 R15.1 R28.1 ; off-sheet ID_A
IMON_MCU: J2.15 ; off-sheet IMON_MCU
MUX_A0: J2.70 U8.1(A0) ; off-sheet MUX_A0
MUX_A1: J2.72 U8.10(A1) ; off-sheet MUX_A1
Prof_GPIO1: J2.62 J4.2 ; off-sheet Prof_GPIO1
Prof_GPIO2: J2.64 J4.1 ; off-sheet Prof_GPIO2
PWM1A: J2.49 ; off-sheet PWM1A
PWM1B: J2.51 ; off-sheet PWM1B
PWM2A: J2.53 ; off-sheet PWM2A
PWM2B: J2.55 ; off-sheet PWM2B
PWM3A: J2.50 ; off-sheet PWM3A
PWM3B: J2.52 ; off-sheet PWM3B
PWM4A: J2.54 ; off-sheet PWM4A
PWM4B: J2.56 ; off-sheet PWM4B
PWM_EN: J2.58 ; off-sheet PWM_EN
RDY: C322.1 J2.69 R79.2 ; off-sheet RDY
RELAY_N: Q3.1(D) Q3.2(D) Q3.5(D) Q3.6(D) Q3.8(D) ; off-sheet RELAY_N
RELAY_P: Q4.1(D) Q4.2(D) Q4.5(D) Q4.6(D) Q4.8(D) ; off-sheet RELAY_P
TEMP_SENSE: J2.68 U8.8(D) ; off-sheet TEMP_SENSE
TMP_HB1_P: R86.2 ; off-sheet TMP_HB1_P
TMP_HB1_S: R30.2 ; off-sheet TMP_HB1_S
TMP_HB2_P: R33.2 ; off-sheet TMP_HB2_P
TMP_HB2_S: R42.2 ; off-sheet TMP_HB2_S
V_DC_PRI: J2.24 ; off-sheet V_DC_PRI
NetC2_1: C2.1 C3.1 C4.1 L1.1 U3.9(VDD)
NetC5_1: C5.1 J5.3 L2.1 R52.1 U3.1(VIO)
NetC9_1: C9.1 C10.2 C11.2 R54.1 R55.2
NetC9_2: C9.2 L3.4 R53.1 R54.2
NetC11_1: C11.1 L3.3 R55.1 R56.1
NetC12_2: C12.2 C13.2 C14.2 L6.2 U3.11(GND2)
NetC121_1: C121.1 R30.1 U8.7(S4)
NetC122_1: C122.1 R33.1 U8.4(S3)
NetC136_1: C136.1 R42.1 U8.9(S2)
NetC137_1: C137.1 R86.1 U8.2(S1)
NetD13_2: D13.2(A) J1.2 Q1.1(D) Q1.2(D) Q1.5(D) Q1.6(D) Q1.8(D)
NetD16_2: D16.2(A) J3.2 Q2.1(D) Q2.2(D) Q2.5(D) Q2.6(D) Q2.8(D)
NetJ2_17: J2.17 R3.2
NetJ2_57: J2.57 R10.2
NetJ2_59: J2.59 R19.2
NetJ2_80: J2.80 R38.1
NetJ2_82: J2.82 R41.1
NetJ6_2: J6.2 R56.2
NetJ6_7: J6.7 R53.2
NetJ6_9: J6.9 J10.1
NetL3_1: L3.1 U3.19(CANH)
NetL3_2: L3.2 U3.18(CANL)
NetQ1_3: Q1.3(G) R1.2 R2.2
NetQ2_3: Q2.3(G) R4.2 R5.2
NetQ3_3: Q3.3(G) R48.2 R51.2
NetQ4_3: Q4.3(G) R39.2 R43.2

Not connected (* = marked no-connect by the designer): J2 1* 2* 3* 4* 5* 6* 8* 11* 12* 18* 20* 21* 26* 27* 28* 29* 30* 31* 32* 33* 34* 36* 37* 39* 40* 41* 42* 43* 44* 45* 66* 71* 73* 74* 75* 76* 77* 78* 85* 86* 87* 88* 89* 90* 91* 93* 95* 96* 104* 106* 107* 108* 109* 110* 113* 114* 115* 116* 117* 118* 119* 120*; J6 1* 8*; U3 2(IN)* 7(NC)* 14(OUT)*

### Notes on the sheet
- (near J2) CONTROL CARD PIN MAPPING
- With this setup DESAT fault can only be removed by power cycling the board.
  Since RST needs to be high to reset DESAT_PRI and DESAT_SEC signal
- (near C73) FAN CONTROL FOR COOLING
- Connect 12 V to provide airflow to heatsinks.
- (near R15) Board Identification Resistors
- (near J4) Profiling GPIO
- (near U8) MUX for Temp Sensing using APWM of Gate driver and thermistor
- Temperature sensing not tested yet
- BATTERY RELAY COONTROL
- CAN Interface not used and not tested yet
- CAN Interface

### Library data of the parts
C1 C4 C6 C12 C313 C319-C322 = CMP-0006848-4: CAP, CERM, 0.01 uF, 100 V, +/- 5%, X7R, 0603; Manufacturer: Kemet; TaMin_C: -55°C; Polarized: N; SizeAreaWB_mm2: 4.68; Value1: Unknown; U/M: EA; Value: 0.01uF; TaMax_C: 125°C; SizeZ_mm: 1; SizeX_mm: 1.6; SizeY_mm: 0.8; SizeArea_mm2: 1.28; AEC Category: Q200
C2 C8 C14 = CMP-0080740-1: CAP, CERM, 10 µF, 25 V,+/- 10%, X7R, 1206; Manufacturer: TDK; Polarized: N; Value: 10uF; U/M: EA; TaMin_C: -55°C; TaMax_C: 125°C; Cap_Case: 1206; SizeArea_mm2: 5.12; SizeAreaWB_mm2: 10.92; SizeX_mm: 3.2; SizeY_mm: 1.6; SizeZ_mm: 1.8; AEC Category: Q200
C3 C7 C13 = CMP-0085302-1: CAP, CERM, 1 µF, 16 V,+/- 10%, X7R, AEC-Q200 Grade 1, 0603; Manufacturer: Samsung Electro-Mechanics; TaMax_C: 125°C; AEC Grade: 1; SizeAreaWB_mm2: 4.68; AEC Category: Q200; SizeY_mm: 0.8; U/M: EA; SizeArea_mm2: 1.28; TaMin_C: -55°C; Value: 1uF; SizeX_mm: 1.6; AEC Qualified: Y; Polarized: N
C5 = CMP-0006837-4: CAP, CERM, 0.1 uF, 50 V, +/- 10%, X7R, 0603; Manufacturer: Wurth Elektronik; TaMin_C: -55°C; Polarized: N; SizeAreaWB_mm2: 4.68; Value1: Unknown; U/M: EA; Value: 0.1uF; TaMax_C: 125°C; SizeZ_mm: 1; SizeX_mm: 1.6; SizeY_mm: 0.8; Value2: 50V; SizeArea_mm2: 1.28; CompType: Capacitor; Cap_F: 100nF; AEC Category: Q200
C9 C11 = CMP-0007220-4: CAP, CERM, 47 pF, 50 V, +/- 5%, C0G/NP0, 0603; Manufacturer: MuRata; TaMin_C: -55°C; Polarized: N; SizeAreaWB_mm2: 4.68; Value1: Unknown; U/M: EA; Value: 47pF; TaMax_C: 125°C; SizeZ_mm: 1; SizeX_mm: 1.6; SizeY_mm: 0.8; SizeArea_mm2: 1.28; AEC Category: Q200
C10 = CMP-0006987-4: CAP, CERM, 4700 pF, 50 V, +/- 10%, X7R, 0603; Manufacturer: Kemet; TaMin_C: -55°C; Polarized: N; SizeAreaWB_mm2: 4.68; Value1: Unknown; U/M: EA; Value: 4700pF; TaMax_C: 125°C; SizeZ_mm: 1; SizeX_mm: 1.6; SizeY_mm: 0.8; SizeArea_mm2: 1.28; AEC Category: Q200
C73 C96 = CMP-0081462-1: as C314 on sheet TIDA-DAB-010054-E4_Power Tree
C121 C122 C136 C137 = CMP-0006839-4: CAP, CERM, 10 pF, 50 V, +/- 5%, C0G/NP0, 0603; Manufacturer: Kemet; TaMin_C: -55°C; Polarized: N; SizeAreaWB_mm2: 4.68; Value1: Unknown; U/M: EA; Value: 10pF; TaMax_C: 125°C; SizeZ_mm: 1; SizeX_mm: 1.6; SizeY_mm: 0.8; SizeArea_mm2: 1.28; AEC Category: Q200
D13 D16 = CMP-0028951-2: Diode, Schottky, 60 V, 0.5 A, SOD-123; Manufacturer: Diodes Inc.; TJmax_C: 150°C; SizeArea_mm2: 6.545; SizeZ_mm: 1.35; Value2: 0.5V; SizeAreaWB_mm2: 13.095; Value: 60V; Green_REACh: Incomplete; Value1: 0.5A; SizeX_mm: 3.85; Vf_V: 500mV; AEC Qualified: N; AEC Category: Q101; SizeY_mm: 1.7; Green_Lifecycle: Not Set; Io_A: 500mA
J1 J3 = CMP-0054787-1: Header, 2.54mm, 2x1, Gold, SMT; Manufacturer: Wurth Elektronik; CNHeader: TRUE; Shrouded: N; Gender: Male; Row_Count: 1; Pitch_mm: 2.54; CT: FALSE
J2 = CMP-0003814-2: C2000 controlCARD-120HSEC connector, SMT; Manufacturer: Samtec; Note: The pin numbering does not match Samtec datasheet
J4 J5 = CMP-0079473-1: Header, 2.54mm, 3x1, Gold, SMT; Manufacturer: Wurth Elektronik; Pitch_mm: 2.54; Gender: Male; Cert_UL: Y; Current_A: 3A; Voltage_V: 250V; Shrouded: N; Row_Count: 1
J6 = CMP-0054820-2: Receptacle, D-Sub, 9 Position, R/A, TH; Manufacturer: Wurth Elektronik; Pitch_mm: 2.77; Gender: Female; Cert_UL: Y; Voltage_V: 125V; ContactFinish: Gold; Row_Count: 2; Current_A: 3A; CNHeader: FALSE; CT: TRUE
J8 J9 = CMP-0055045-1: Shorting Jumper, 7.62mm, 2 Position, Gold, TH; Manufacturer: Mill-Max; CNHeader: FALSE; Gender: Male; Pitch_mm: 7.62; Cert_UL: Y
J10 = CMP-0054794-2: Header, 2.54 mm, 2x1, Gold, TH; Manufacturer: Wurth Elektronik; Shrouded: N; Gender: Male; Green_REACh: Passed; Pitch_mm: 2.54; Green_Lifecycle: Active; Row_Count: 1; Cert_UL: Y
L1 L2 L4-L6 = CMP-0003155-2: Ferrite Bead, 26 ohm @ 100 MHz, 6.5 A, 0603; Manufacturer: Wurth Elektronik; Ztyp@1GHz_Ohm: 35.506; ZTyp@100MHz_Ohm: 26; SizeAreaWB_mm2: 4.68; DCR_ohm: 5m; Value1: 0.005 ohm; Value: 26 ohm; Imax_A: 6.5A; SizeZ_mm: 1; SizeX_mm: 1.6; SizeY_mm: 0.8; SizeArea_mm2: 1.28
L3 = CMP-0084086-1: 100µH @ 100kHz 2 Line Common Mode Choke Surface Mount 5.8 kOhms @ 10MHz 150mA DCR 2Ohm; Manufacturer: TDK; AEC Grade: Grade 0; Tolerance_%: +50/-30%; AEC Qualified: Yes; Ind_H: 100uH; SizeZ_mm: 3mm; DCR_ohm: 2Ω; Impedance At Frequency: 5800Ω @ 10MHz; Imax_A: 0.15A
Q1-Q4 = CMP-0076725-1: 30-V N-Channel NexFET™ Power MOSFET; Manufacturer: Texas Instruments; VdsMax_V: 30V; SizeZ_mm: 0.8mm; ChMode: False; QgTyp_nC: 6nC @ 4.5V; Rdson45_ohm: 13.9m; Vgs_V: 10V; AEC Qualified: No; IdsMax_A: 10A
R1 R4 R39 R48 = CMP-0023921-2: RES, 200, 0.1%, 0.1 W, 0603; Manufacturer: Yageo America; Power_W: 100mW; TempCo: 25 ppm/C; Value_Code: 200R; U/M: EA; Value: 200; EIA_Code: E192; SizeX_mm: 1.6; SizeY_mm: 0.8; SizeZ_mm: 1; Value2: 0.1W; SizeArea_mm2: 1.28; VDC_V: 75V; AEC Category: Q200
R2 R5 R43 R51 = CMP-0023653-3: RES, 10.0 k, 0.1%, 0.1 W, 0603; Manufacturer: Yageo America; Power_W: 100mW; TempCo: 25 ppm/C; Value_Code: 10k0; U/M: EA; Value: 10.0k; EIA_Code: E192; Res_ohm: 10k; SizeX_mm: 1.6; SizeY_mm: 0.8; SizeZ_mm: 1; Value2: 0.1W; SizeArea_mm2: 1.28; CompType: Resistor; VDC_V: 75V; AEC Category: Q200
R3 R10 R15 R19 R38 R41 = CMP-0023343-3: RES, 0, 1%, 0.1 W, AEC-Q200 Grade 0, 0603; Manufacturer: Stackpole Electronics Inc; Power_W: 100mW; TempCo: ppm/C; U/M: EA; Value: 0; SizeX_mm: 1.6; SizeY_mm: 0.8; SizeZ_mm: 1; Value2: 0.1W; SizeArea_mm2: 1.28; CompType: Resistor; AEC Qualified: Y; AEC Category: Q200
R28 R52 R79 R82 R204 R205 = CMP-0021998-4: RES, 10.0 k, 1%, 0.1 W, AEC-Q200 Grade 0, 0603; Manufacturer: Vishay-Dale; Value: 10.0k; Res_ohm: 10k; Value_Code: 10k0; Power_W: 100mW; Value2: 0.1W; VDC_V: 75V; TempCo: 100 ppm/C; SizeArea_mm2: 1.28; SizeX_mm: 1.6; SizeY_mm: 0.8; SizeZ_mm: 1; EIA_Code: E96; AEC Category: Q200; AEC Qualified: Y; AEC Grade: 0
R30 R33 R42 R86 = CMP-0023143-5: RES, 49.9, 1%, 0.1 W, 0603; Manufacturer: Yageo; Power_W: 100mW; TempCo: 100 ppm/C; Value_Code: 49R9; Value: 49.9; EIA_Code: E96; SizeX_mm: 1.6; SizeY_mm: 0.8; SizeZ_mm: 1; Value2: 0.1W; SizeArea_mm2: 1.28; AEC Qualified: N; VDC_V: 75V; AEC Category: Q200; SizeAreaWB_mm2: 4.68
R53 R56 = CMP-0094956-1: 0 Ohms Jumper 0.1W, 1/10W Chip Resistor 0603 (1608 Metric) - Thick Film; Manufacturer: Venkel; Value: 0uΩ; Res_ohm: 0; Power_W: 100mW; SizeZ_mm: 0.55mm; AEC Qualified: No
R54 R55 = CMP-0022500-4: RES, 56.2, 1%, 0.1 W, AEC-Q200 Grade 0, 0603; Manufacturer: Vishay-Dale; Power_W: 100mW; TempCo: 100 ppm/C; Value_Code: 56R2; Value: 56.2; EIA_Code: E96; SizeX_mm: 1.6; SizeY_mm: 0.8; SizeZ_mm: 1; Value2: 0.1W; SizeArea_mm2: 1.28; AEC Qualified: Y; VDC_V: 75V; AEC Category: Q200; AEC Grade: 0
TP12 TP20-TP23 TP25-TP29 = CMP-0055152-2: as TP6 on sheet TIDA-DAB-010054-E4_Power Tree
U1 = CMP-0051219-1: Single 3-Input Positive-AND Gate, DBV0006A, LARGE T&R; Manufacturer: Texas Instruments; Output Type: CMOS; Voltage(Nom)(V): 1.8,2.5,3.3,5; ICC @ Nom Voltage(Max)(mA): 0.01; VCC(Min)(V): 1.65; Output Drive (IOL/IOH)(Max)(mA): 32/-32; Schmitt Trigger: No; Input Type: CMOS/TTL; VCC(Max)(V): 5.5; Gate Type: AND; Rating: Catalog; tpd @ Nom Voltage(Max)(ns): 20,7.8,6.2,4.6; Bits(#): 1; F @ Nom Voltage(Max)(Mhz): 150; Logic: True; Technology Family: LVC
U3 = CMP-0092023-2: Reinforced 5-kVRMS Isolated CAN Transceiver with Integrated lowemissions DC-DC Converter; Manufacturer: Texas Instruments; TJmax_C: +150°C; Max Supply Voltage: 5.5V; AEC Qualified: No; Standoff Height: 0.1mm; Nominal Supply Current: 0.3-124mA; CompType: IC; AEC Category: Q200; TaMax_C: +105°C; SizeZ_mm: 3.55mm; Min Supply Voltage: 1.71V; TaMin_C: -40°C
U8 = CMP-0088302-2: , 4:1, General Purpose Analog Multiplexer; Manufacturer: Texas Instruments; Min Supply Voltage: 1.08V; TaMax_C: +125°C; Max Supply Voltage: 5.5V; TJmax_C: +150°C; SizeZ_mm: 1.1mm; AEC Qualified: No; PositionCount: 1; TaMin_C: -40°C; Nominal Supply Current: 0.01uA; CompType: IC; -3Db Bandwith: 125MHz; AEC Category: Q200; On State Resistance: 5Ω; Standoff Height: 0.05mm

## Sheet TIDA-DAB-010054-E4_EVM_Hardware.SchDoc
size 431 x 279 mm; Date: Not shown in title block; ApprovedBy: Not shown in title block; CheckedBy: Not shown in title block; Author: Not shown in title block; CompanyName: Not shown in title block; Engineer: Not shown in title block; Organization: Not shown in title block; Address1: Not shown in title block; Address2: Not shown in title block; Address3: Not shown in title block; Address4: Not shown in title block; DocumentNumber: 1; Revision: Use project parameter SCH_Rev; SheetNumber: 11; SheetTotal: 11; PageSetup: Record=PageOptions¦CenterHorizontal=True¦CenterVertical=True¦PrintScale=1.00¦XCorrection=1.00¦YCorrection=1.00¦PrintKind=0¦BorderSize=5000000¦LeftOffset=0¦BottomOffset=0¦Orientation=2¦PaperLength=1000¦PaperWidth=1000¦Scale=100¦PaperSource=15¦PrintQuality=600¦MediaType=1¦DitherType=10¦PaperKind=Letter¦PrintScaleMode=1
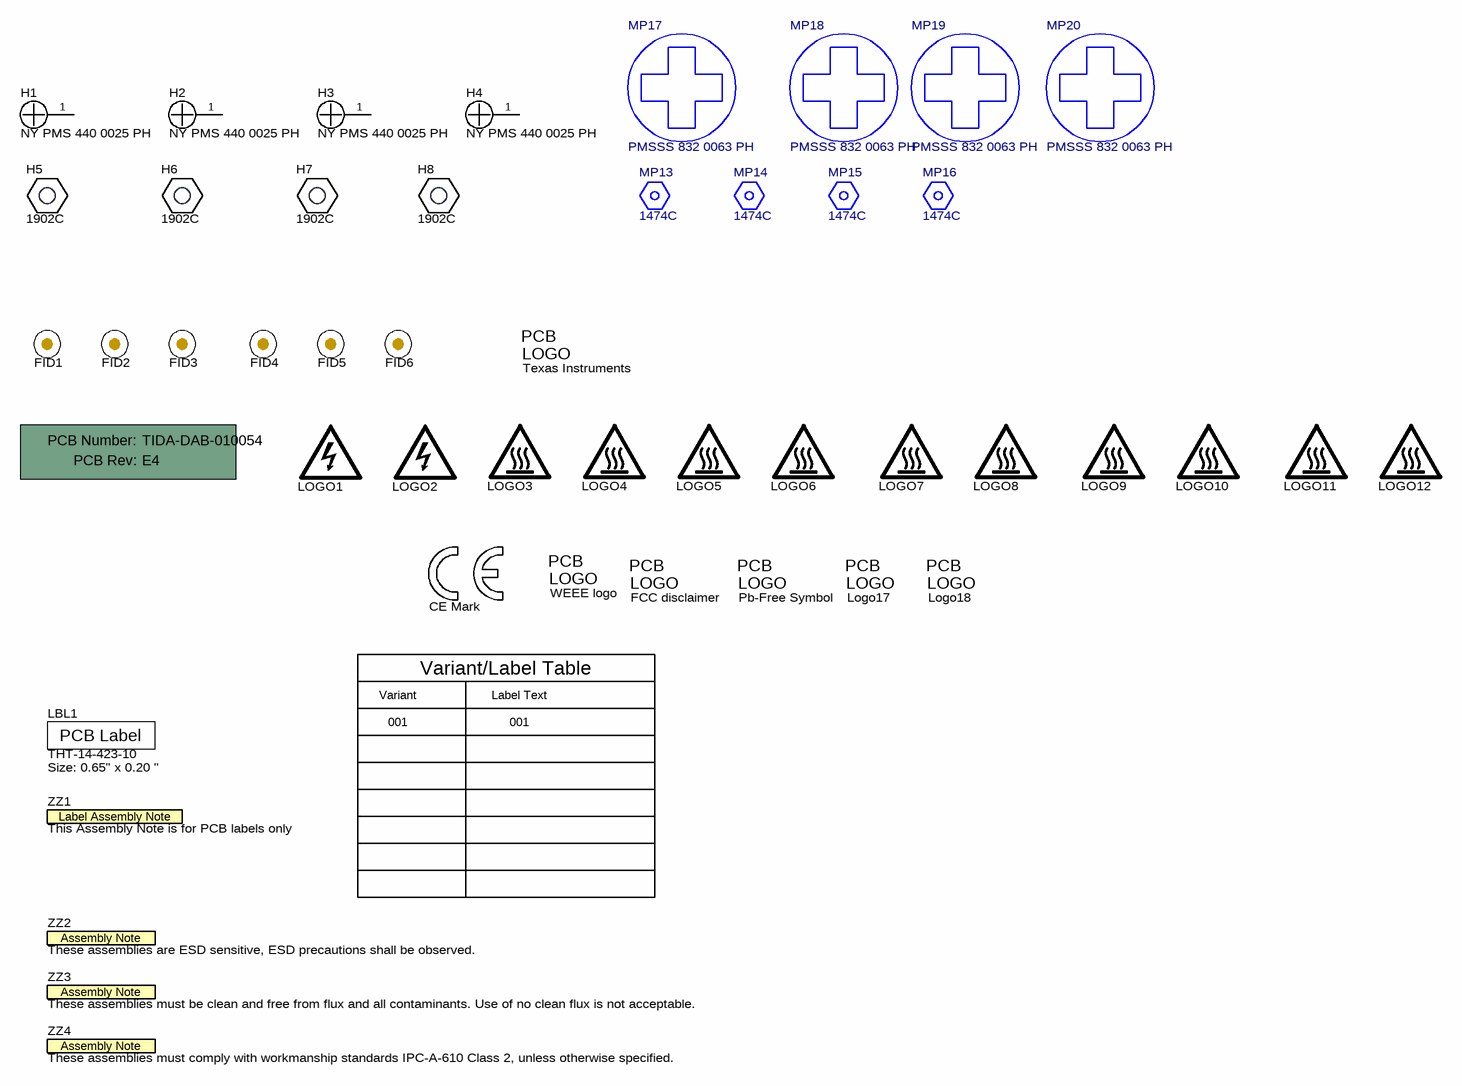
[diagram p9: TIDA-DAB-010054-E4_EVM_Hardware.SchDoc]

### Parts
!PCB1  Printed Circuit Board  (value not drawn)  (mechanical)
FID1  Fiducial  [Fiducial10-20]  (value not drawn)
FID2  Fiducial  [Fiducial10-20]  (value not drawn)
FID3  Fiducial  [Fiducial10-20]  (value not drawn)
FID4  Fiducial  [Fiducial10-20]  (value not drawn)
FID5  Fiducial  [Fiducial10-20]  (value not drawn)
FID6  Fiducial  [Fiducial10-20]  (value not drawn)
H1  NY PMS 440 0025 PH  [NY PMS 440 0025 PH]
H2  NY PMS 440 0025 PH  [NY PMS 440 0025 PH]
H3  NY PMS 440 0025 PH  [NY PMS 440 0025 PH]
H4  NY PMS 440 0025 PH  [NY PMS 440 0025 PH]
H5  1902C  [Keystone_1902C]
H6  1902C  [Keystone_1902C]
H7  1902C  [Keystone_1902C]
H8  1902C  [Keystone_1902C]
LBL1  THT-14-423-10  Note: Size: 0.65" x 0.20 "  [Label_650x200]
LOGO1  DANGER HIGH VOLTAGE  [IEC_HighVoltage_Medium]  (value not drawn)  (no BOM)
LOGO2  DANGER HIGH VOLTAGE  [IEC_HighVoltage_Medium]  (value not drawn)  (no BOM)
LOGO3  CAUTION HOT SURFACE  [IEC_HotSurface_Small]  (value not drawn)  (no BOM)
LOGO4  CAUTION HOT SURFACE  [IEC_HotSurface_Small]  (value not drawn)  (no BOM)
LOGO5  CAUTION HOT SURFACE  [IEC_HotSurface_Small]  (value not drawn)  (no BOM)
LOGO6  CAUTION HOT SURFACE  [IEC_HotSurface_Small]  (value not drawn)  (no BOM)
LOGO7  CAUTION HOT SURFACE  [IEC_HotSurface_Small]  (value not drawn)  (no BOM)
LOGO8  CAUTION HOT SURFACE  [IEC_HotSurface_Small]  (value not drawn)  (no BOM)
LOGO9  CAUTION HOT SURFACE  [IEC_HotSurface_Small]  (value not drawn)  (no BOM)
LOGO10  CAUTION HOT SURFACE  [IEC_HotSurface_Small]  (value not drawn)  (no BOM)
LOGO11  CAUTION HOT SURFACE  [IEC_HotSurface_Small]  (value not drawn)  (no BOM)
LOGO12  CAUTION HOT SURFACE  [IEC_HotSurface_Small]  (value not drawn)  (no BOM)
Logo13  CE Mark  [CE_Mark_5mm]  (no BOM)
Logo14  WEEE logo  [WEEE_Minimum]  (no BOM)
Logo15  FCC disclaimer  [FCC_disclaimer]  (no BOM)
Logo16  Pb-Free Symbol  [Pb-Free_Overlay_Medium]  (no BOM)
Logo17  CAUTION.  READ USER GUIDE BEFORE USE  [IEC_Caution_Medium]  (value not drawn)  (no BOM)
Logo18  ESD Susceptible  [ESD_Overlay_Medium]  (value not drawn)  (no BOM)
Logo19  Texas Instruments  [TI_Stacked_Overlay_Small]  (no BOM)
MP13  1474C  [FP-1474C_HEX_STANDOFF_8-32_1IN2-MFG]
MP14  1474C  [FP-1474C_HEX_STANDOFF_8-32_1IN2-MFG]
MP15  1474C  [FP-1474C_HEX_STANDOFF_8-32_1IN2-MFG]
MP16  1474C  [FP-1474C_HEX_STANDOFF_8-32_1IN2-MFG]
MP17  PMSSS 832 0063 PH  [FP-PMSSS 832 0063 PH_SCREW_0IN322-MFG]
MP18  PMSSS 832 0063 PH  [FP-PMSSS 832 0063 PH_SCREW_0IN322-MFG]
MP19  PMSSS 832 0063 PH  [FP-PMSSS 832 0063 PH_SCREW_0IN322-MFG]
MP20  PMSSS 832 0063 PH  [FP-PMSSS 832 0063 PH_SCREW_0IN322-MFG]
ZZ1  This Assembly Note is for PCB labels only  [AssemblyNoteLabel]  (no BOM)
ZZ2  These assemblies are ESD sensitive, ESD precautions shall be observed.  [AssemblyNote]  (no BOM)
ZZ3  These assemblies must be clean and free from flux and all contaminants. Use of no clean flux is not acceptable.  [AssemblyNote]  (no BOM)
ZZ4  These assemblies must comply with workmanship standards IPC-A-610 Class 2, unless otherwise specified.  [AssemblyNote]  (no BOM)

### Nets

Not connected (* = marked no-connect by the designer): H1 1; H2 1; H3 1; H4 1

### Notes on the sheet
- Variant
- Variant/Label Table
- Label Text
- 001

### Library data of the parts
!PCB1 = CMP-0003618-2: Manufacturer: Any; PartNumber: TIDA-DAB-010054
FID1-FID6 = CMP-0077181-1: Fiducial mark.  There is nothing to buy or mount.
H1-H4 = CMP-0003617-1: Machine Screw, Round, #4-40 x 1/4, Nylon, Philips panhead; Manufacturer: B&F Fastener Supply; CompType: Hardware
H5-H8 = CMP-0003610-1: Standoff, Hex, 0.5"L #4-40 Nylon; Manufacturer: Keystone; CompType: Hardware
LBL1 = CMP-0003625-1: Thermal Transfer Printable Labels, 0.650" W x 0.200" H - 10,000 per roll; Manufacturer: Brady; CompType: Label
LOGO1 LOGO2 = CMP-0074835-1: IEC 61010-1 High Voltage Warning; SymbolCreator: a0412235; Lib Reference: IEC_HighVoltage
LOGO3-LOGO12 = CMP-0074837-1: IEC 61010-1 Hot Surface Warning; SymbolCreator: a0412235; Lib Reference: IEC_HotSurface
Logo13 = CMP-0074844-1: SymbolCreator: a0412235
Logo14 = CMP-0074769-1
Logo15 = CMP-0074847-1: FCC_disclaimer
Logo16 = CMP-0074839-1: SymbolCreator: a0412235
Logo17 = CMP-0074836-1: IEC 61010-1 Caution Warning; SymbolCreator: a0412235; Lib Reference: IEC_Caution; Library Reference: Logo
Logo18 = CMP-0074840-1: ESD Susceptible Symbol; SymbolCreator: a0412235; Lib Reference: ESD_Susceptible; Library Reference: Logo
Logo19 = CMP-0074838-1: Texas Instrument Corporate Signature; SymbolCreator: a0412235; Lib Reference: TI_Logo; Library Reference: Logo
MP13-MP16 = CMP-0120966-2: Hex Standoff Threaded #8-32 Brass 0.500" (12.70mm) 1/2"; Manufacturer: Keystone Electronics; AEC Qualified: No; SizeZ_mm: 0.505inch
MP17-MP20 = CMP-0093555-1: #8-32 Pan Head Machine Screw Phillips Drive Stainless Steel; Manufacturer: Building Fasteners; AEC Qualified: No
ZZ1 = CMP-0003616-3
ZZ2 = CMP-0077236-1
ZZ3 = CMP-0077237-1
ZZ4 = CMP-0077238-1

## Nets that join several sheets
1V65_1: TIDA-DAB-010054-E4_PrimarySideSensing (7 pins), TIDA-DAB-010054-E4_Control Card (R3.1)
3V3_A: TIDA-DAB-010054-E4_PrimarySideSensing (11 pins), TIDA-DAB-010054-E4_SecondarySideSensing (5 pins), TIDA-DAB-010054-E4_Power Tree (C65.1 U5.5), TIDA-DAB-010054-E4_Control Card (R15.2)
3V3_D: TIDA-DAB-010054-E4_PrimarySideSensing (R164.2), TIDA-DAB-010054-E4_SecondarySideSensing (L8.2 L9.2 L10.2 R123.2), TIDA-DAB-010054-E4_GateDriverPrimHB1 (9 pins), TIDA-DAB-010054-E4_GateDriverPrimHB2 (8 pins), TIDA-DAB-010054-E4_GateDriverSecHB1 (9 pins), TIDA-DAB-010054-E4_GateDriverSecHB2 (8 pins), TIDA-DAB-010054-E4_Power Tree (C69.1 U6.5), TIDA-DAB-010054-E4_Control Card (10 pins)
5V: TIDA-DAB-010054-E4_Power Tree (24 pins), TIDA-DAB-010054-E4_Control Card (5 pins)
12V: TIDA-DAB-010054-E4_PowerStage (6 pins), TIDA-DAB-010054-E4_GateDriverPrimHB1 (12 pins), TIDA-DAB-010054-E4_GateDriverPrimHB2 (12 pins), TIDA-DAB-010054-E4_GateDriverSecHB1 (12 pins), TIDA-DAB-010054-E4_GateDriverSecHB2 (12 pins), TIDA-DAB-010054-E4_Power Tree (14 pins), TIDA-DAB-010054-E4_Control Card (6 pins)
+15V_BOT1: TIDA-DAB-010054-E4_PrimarySideSensing (R129.1), TIDA-DAB-010054-E4_GateDriverPrimHB1 (13 pins), TIDA-DAB-010054-E4_GateDriverPrimHB2 (R227.1)
+15V_BOT4: TIDA-DAB-010054-E4_GateDriverSecHB1 (R338.1), TIDA-DAB-010054-E4_GateDriverSecHB2 (13 pins)
+15V_SEN_SEC: TIDA-DAB-010054-E4_SecondarySideSensing (R88.1), TIDA-DAB-010054-E4_GateDriverSecHB1 (R339.2)
-4V_BOT1: TIDA-DAB-010054-E4_PrimarySideSensing (C119.2 C120.1 R14.2 R131.1), TIDA-DAB-010054-E4_GateDriverPrimHB1 (25 pins), TIDA-DAB-010054-E4_GateDriverPrimHB2 (R219.1)
-4V_BOT4: TIDA-DAB-010054-E4_GateDriverSecHB1 (R379.1), TIDA-DAB-010054-E4_GateDriverSecHB2 (25 pins)
-4V_SEN_SEC: TIDA-DAB-010054-E4_SecondarySideSensing (C90.2 C91.1 R13.2 R87.1), TIDA-DAB-010054-E4_GateDriverSecHB1 (R380.2)
GND: TIDA-DAB-010054-E4_PowerStage (C60.1 C61.2 C138.2 C145.2), TIDA-DAB-010054-E4_PrimarySideSensing (29 pins), TIDA-DAB-010054-E4_SecondarySideSensing (20 pins), TIDA-DAB-010054-E4_GateDriverPrimHB1 (61 pins), TIDA-DAB-010054-E4_GateDriverPrimHB2 (50 pins), TIDA-DAB-010054-E4_GateDriverSecHB1 (61 pins), TIDA-DAB-010054-E4_GateDriverSecHB2 (50 pins), TIDA-DAB-010054-E4_Power Tree (34 pins), TIDA-DAB-010054-E4_Control Card (49 pins)
GND_BOT1: TIDA-DAB-010054-E4_PowerStage (Q12.3), TIDA-DAB-010054-E4_PrimarySideSensing (19 pins), TIDA-DAB-010054-E4_GateDriverPrimHB1 (10 pins), TIDA-DAB-010054-E4_GateDriverPrimHB2 (R224.1)
GND_BOT2: TIDA-DAB-010054-E4_PowerStage (Q13.3), TIDA-DAB-010054-E4_GateDriverPrimHB2 (11 pins)
GND_BOT3: TIDA-DAB-010054-E4_PowerStage (Q10.3), TIDA-DAB-010054-E4_GateDriverSecHB1 (11 pins)
GND_BOT4: TIDA-DAB-010054-E4_PowerStage (Q11.3), TIDA-DAB-010054-E4_GateDriverSecHB1 (R341.1), TIDA-DAB-010054-E4_GateDriverSecHB2 (10 pins)
GND_SEN_SEC: TIDA-DAB-010054-E4_SecondarySideSensing (26 pins), TIDA-DAB-010054-E4_GateDriverSecHB1 (R342.2)
GND_TOP1: TIDA-DAB-010054-E4_PowerStage (Q9.3), TIDA-DAB-010054-E4_GateDriverPrimHB1 (11 pins)
GND_TOP2: TIDA-DAB-010054-E4_PowerStage (Q8.3), TIDA-DAB-010054-E4_GateDriverPrimHB2 (11 pins)
GND_TOP3: TIDA-DAB-010054-E4_PowerStage (Q6.3), TIDA-DAB-010054-E4_GateDriverSecHB1 (11 pins)
GND_TOP4: TIDA-DAB-010054-E4_PowerStage (Q7.3), TIDA-DAB-010054-E4_GateDriverSecHB2 (11 pins)
PGND: TIDA-DAB-010054-E4_PowerStage (16 pins), TIDA-DAB-010054-E4_PrimarySideSensing (6 pins)
SGND: TIDA-DAB-010054-E4_PowerStage (16 pins), TIDA-DAB-010054-E4_SecondarySideSensing (5 pins)
VIN_AUX: TIDA-DAB-010054-E4_Power Tree (10 pins), TIDA-DAB-010054-E4_Control Card (J8.1)
~{DESAT_PRI}: TIDA-DAB-010054-E4_GateDriverPrimHB1 (R147.1 R150.1), TIDA-DAB-010054-E4_GateDriverPrimHB2 (R212.1 R213.1), TIDA-DAB-010054-E4_Control Card (5 pins)
~{DESAT_SEC}: TIDA-DAB-010054-E4_GateDriverSecHB1 (R206.1 R207.1), TIDA-DAB-010054-E4_GateDriverSecHB2 (R263.1 R264.1), TIDA-DAB-010054-E4_Control Card (5 pins)
~{FLT_PRI}: TIDA-DAB-010054-E4_PrimarySideSensing (C324.2 R164.1 R167.2), TIDA-DAB-010054-E4_Control Card (J2.79)
~{FLT_SEC}: TIDA-DAB-010054-E4_SecondarySideSensing (C323.2 R123.1 R125.2), TIDA-DAB-010054-E4_Control Card (J2.81)
~{RST}: TIDA-DAB-010054-E4_GateDriverPrimHB1 (R214.1 R220.1), TIDA-DAB-010054-E4_GateDriverPrimHB2 (R323.1 R324.1), TIDA-DAB-010054-E4_GateDriverSecHB1 (R279.1 R280.1), TIDA-DAB-010054-E4_GateDriverSecHB2 (R375.1 R376.1), TIDA-DAB-010054-E4_Control Card (TP22.1 U1.4)
CLK_MOD: TIDA-DAB-010054-E4_SecondarySideSensing (5 pins), TIDA-DAB-010054-E4_Control Card (R10.1)
D1H_P: TIDA-DAB-010054-E4_PowerStage (11 pins), TIDA-DAB-010054-E4_PrimarySideSensing (R112.1), TIDA-DAB-010054-E4_GateDriverPrimHB1 (D14.1), TIDA-DAB-010054-E4_GateDriverPrimHB2 (D26.1)
D1H_S: TIDA-DAB-010054-E4_PowerStage (11 pins), TIDA-DAB-010054-E4_SecondarySideSensing (R96.2), TIDA-DAB-010054-E4_GateDriverSecHB1 (D18.1), TIDA-DAB-010054-E4_GateDriverSecHB2 (D25.1)
D1L_P: TIDA-DAB-010054-E4_PowerStage (16 pins), TIDA-DAB-010054-E4_GateDriverPrimHB1 (D15.1)
D1L_S: TIDA-DAB-010054-E4_PowerStage (Q6.2 Q10.1), TIDA-DAB-010054-E4_SecondarySideSensing (U2.2), TIDA-DAB-010054-E4_GateDriverSecHB1 (D19.1)
D2L_P: TIDA-DAB-010054-E4_PowerStage (Q8.2 Q13.1), TIDA-DAB-010054-E4_PrimarySideSensing (U15.1), TIDA-DAB-010054-E4_GateDriverPrimHB2 (D22.1)
D2L_S: TIDA-DAB-010054-E4_PowerStage (16 pins), TIDA-DAB-010054-E4_GateDriverSecHB2 (D27.1)
DOUT_I_DC_SEC: TIDA-DAB-010054-E4_SecondarySideSensing (C93.1 R92.2 TP13.1), TIDA-DAB-010054-E4_Control Card (J2.100)
DOUT_V_BATT_SEC: TIDA-DAB-010054-E4_SecondarySideSensing (C107.1 R116.2 TP14.1), TIDA-DAB-010054-E4_Control Card (J2.99)
DOUT_V_DC_SEC: TIDA-DAB-010054-E4_SecondarySideSensing (C108.1 R117.2 TP15.1), TIDA-DAB-010054-E4_Control Card (J2.103)
G1H_P: TIDA-DAB-010054-E4_PowerStage (Q9.4), TIDA-DAB-010054-E4_GateDriverPrimHB1 (R209.2 R216.2 U29.7)
G1H_S: TIDA-DAB-010054-E4_PowerStage (Q6.4), TIDA-DAB-010054-E4_GateDriverSecHB1 (R272.2 R275.2 U34.7)
G1L_P: TIDA-DAB-010054-E4_PowerStage (Q12.4), TIDA-DAB-010054-E4_GateDriverPrimHB1 (R215.2 R218.2 U30.7)
G1L_S: TIDA-DAB-010054-E4_PowerStage (Q10.4), TIDA-DAB-010054-E4_GateDriverSecHB1 (R274.2 R277.2 U35.7)
G2H_P: TIDA-DAB-010054-E4_PowerStage (Q8.4), TIDA-DAB-010054-E4_GateDriverPrimHB2 (R316.2 R319.2 U37.7)
G2H_S: TIDA-DAB-010054-E4_PowerStage (Q7.4), TIDA-DAB-010054-E4_GateDriverSecHB2 (R368.2 R371.2 U40.7)
G2L_P: TIDA-DAB-010054-E4_PowerStage (Q13.4), TIDA-DAB-010054-E4_GateDriverPrimHB2 (R318.2 R321.2 U38.7)
G2L_S: TIDA-DAB-010054-E4_PowerStage (Q11.4), TIDA-DAB-010054-E4_GateDriverSecHB2 (R370.2 R373.2 U41.7)
I_DC_PRI: TIDA-DAB-010054-E4_PrimarySideSensing (C128.1 R139.2 TP8.1), TIDA-DAB-010054-E4_Control Card (J2.14)
I_OUT_N: TIDA-DAB-010054-E4_PowerStage (R59.2), TIDA-DAB-010054-E4_SecondarySideSensing (R91.1)
I_OUT_P: TIDA-DAB-010054-E4_PowerStage (R59.1), TIDA-DAB-010054-E4_SecondarySideSensing (R89.1)
I_PRI_P: TIDA-DAB-010054-E4_PowerStage (T1.2), TIDA-DAB-010054-E4_PrimarySideSensing (U15.2)
I_SEC_P: TIDA-DAB-010054-E4_PowerStage (T1.3), TIDA-DAB-010054-E4_SecondarySideSensing (U2.1)
I_TANK_PRI: TIDA-DAB-010054-E4_PrimarySideSensing (C153.1 R168.2 TP19.1), TIDA-DAB-010054-E4_Control Card (J2.25)
I_TANK_SEC: TIDA-DAB-010054-E4_SecondarySideSensing (C114.1 R126.2 TP17.1), TIDA-DAB-010054-E4_Control Card (J2.23)
Iin+: TIDA-DAB-010054-E4_PowerStage (R58.3), TIDA-DAB-010054-E4_PrimarySideSensing (R136.1)
Iin-: TIDA-DAB-010054-E4_PowerStage (R58.4), TIDA-DAB-010054-E4_PrimarySideSensing (R140.1)
IMON_MCU: TIDA-DAB-010054-E4_Power Tree (R72.2 TP10.1), TIDA-DAB-010054-E4_Control Card (J2.15)
PWM1A: TIDA-DAB-010054-E4_GateDriverPrimHB1 (R182.2 U26.2), TIDA-DAB-010054-E4_Control Card (J2.49)
PWM1B: TIDA-DAB-010054-E4_GateDriverPrimHB1 (R181.2 U26.5), TIDA-DAB-010054-E4_Control Card (J2.51)
PWM2A: TIDA-DAB-010054-E4_GateDriverPrimHB1 (R180.2 U26.9), TIDA-DAB-010054-E4_Control Card (J2.53)
PWM2A_1: TIDA-DAB-010054-E4_GateDriverPrimHB1 (PWM3.1 R175.2 U26.8), TIDA-DAB-010054-E4_GateDriverPrimHB2 (R303.1 R306.1)
PWM2B: TIDA-DAB-010054-E4_GateDriverPrimHB1 (R179.2 U26.12), TIDA-DAB-010054-E4_Control Card (J2.55)
PWM2B_1: TIDA-DAB-010054-E4_GateDriverPrimHB1 (PWM4.1 R174.2 U26.11), TIDA-DAB-010054-E4_GateDriverPrimHB2 (R304.1 R305.1)
PWM3A: TIDA-DAB-010054-E4_GateDriverSecHB1 (R239.2 U31.2), TIDA-DAB-010054-E4_Control Card (J2.50)
PWM3B: TIDA-DAB-010054-E4_GateDriverSecHB1 (R238.2 U31.5), TIDA-DAB-010054-E4_Control Card (J2.52)
PWM4A: TIDA-DAB-010054-E4_GateDriverSecHB1 (R237.2 U31.9), TIDA-DAB-010054-E4_Control Card (J2.54)
PWM4A_1: TIDA-DAB-010054-E4_GateDriverSecHB1 (PWM7.1 R233.2 U31.8), TIDA-DAB-010054-E4_GateDriverSecHB2 (R352.1 R355.1)
PWM4B: TIDA-DAB-010054-E4_GateDriverSecHB1 (R236.2 U31.12), TIDA-DAB-010054-E4_Control Card (J2.56)
PWM4B_1: TIDA-DAB-010054-E4_GateDriverSecHB1 (PWM8.1 R232.2 U31.11), TIDA-DAB-010054-E4_GateDriverSecHB2 (R353.1 R354.1)
PWM_EN: TIDA-DAB-010054-E4_GateDriverPrimHB1 (R173.1), TIDA-DAB-010054-E4_GateDriverSecHB1 (R231.1), TIDA-DAB-010054-E4_Control Card (J2.58)
RDY: TIDA-DAB-010054-E4_GateDriverPrimHB1 (R85.1 R144.1), TIDA-DAB-010054-E4_GateDriverPrimHB2 (R210.1 R211.1), TIDA-DAB-010054-E4_GateDriverSecHB1 (R193.1 R194.1), TIDA-DAB-010054-E4_GateDriverSecHB2 (R251.1 R252.1), TIDA-DAB-010054-E4_Control Card (C322.1 J2.69 R79.2)
RELAY_N: TIDA-DAB-010054-E4_PowerStage (D4.1 K3.1), TIDA-DAB-010054-E4_Control Card (5 pins)
RELAY_P: TIDA-DAB-010054-E4_PowerStage (D2.1 K1.1), TIDA-DAB-010054-E4_Control Card (5 pins)
TMP_HB1_P: TIDA-DAB-010054-E4_GateDriverPrimHB1 (U29.16), TIDA-DAB-010054-E4_Control Card (R86.2)
TMP_HB1_S: TIDA-DAB-010054-E4_GateDriverSecHB1 (U34.16), TIDA-DAB-010054-E4_Control Card (R30.2)
TMP_HB2_P: TIDA-DAB-010054-E4_GateDriverPrimHB2 (U37.16), TIDA-DAB-010054-E4_Control Card (R33.2)
TMP_HB2_S: TIDA-DAB-010054-E4_GateDriverSecHB2 (U40.16), TIDA-DAB-010054-E4_Control Card (R42.2)
V_DC_PRI: TIDA-DAB-010054-E4_PrimarySideSensing (C140.2 R157.2 TP9.1), TIDA-DAB-010054-E4_Control Card (J2.24)
VBATT_N: TIDA-DAB-010054-E4_PowerStage (J14.1 K3.3 TP5.1), TIDA-DAB-010054-E4_SecondarySideSensing (R100.1)
VBATT_P: TIDA-DAB-010054-E4_PowerStage (J12.1 K1.3 TP2.1), TIDA-DAB-010054-E4_SecondarySideSensing (R101.2)

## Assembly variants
001: not fitted C42 C43 C44 C47 C53 C54 C55 C56 C83 C84 C90 C92 C115 C119 C123 C123 C125 C127 C127 C133 C134 C193 C194 C195 C263 C271 C272 C272 C273 C273 D24 D28 D29 D30 L1 R6 R7 R20 R21 R170 R219 R221 R224 R225 R227 R229 R340 R343 R381 R?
